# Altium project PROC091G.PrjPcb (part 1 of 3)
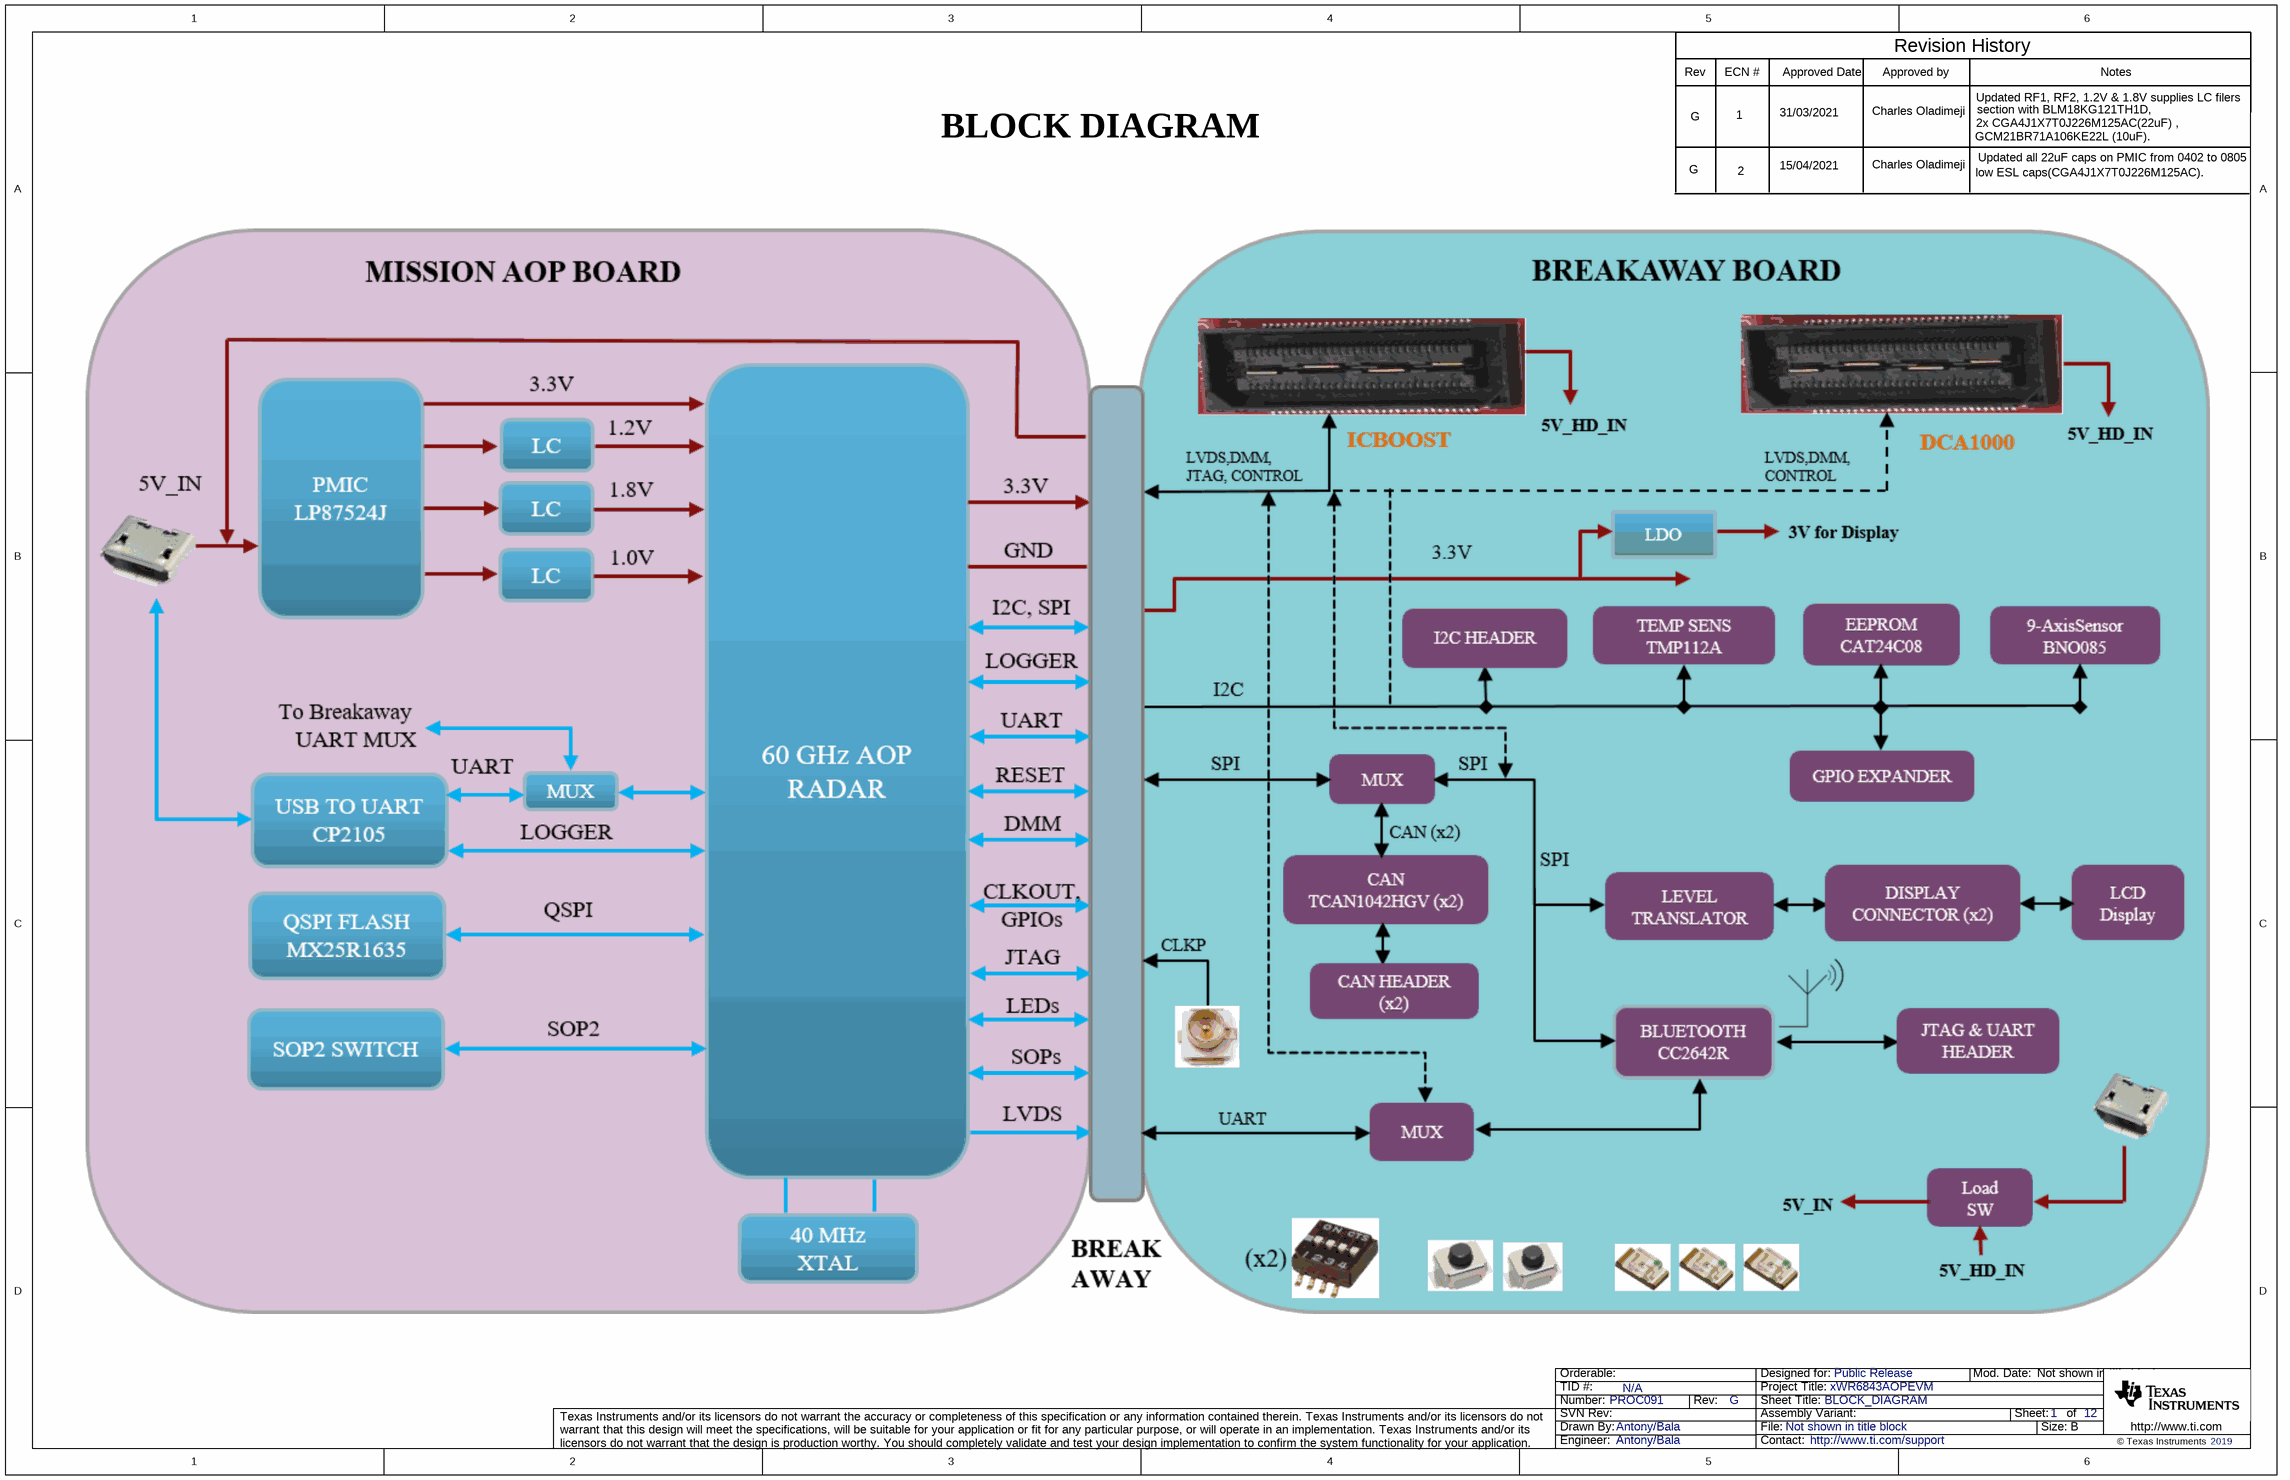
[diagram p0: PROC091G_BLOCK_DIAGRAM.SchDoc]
CopyrightYear: 2019; PCB_Layout: Mistral Team; PCB_Rev: G; PRJ_Customer: Public Release; PRJ_Engineer: Antony/Bala; PRJ_Number: PROC091; PRJ_Title: xWR6843AOPEVM; SCH_Rev: G; TechSupport: http://www.ti.com/support; TID: N/A
12 sheets, 442 parts. Net scope: flat (ports and power ports of the same name join across sheets).
Board file: PROC091G.PcbDoc
Sheets:
  PROC091G_BLOCK_DIAGRAM.SchDoc
  PROC091G_TABLEOFCONTENTS.SchDoc
  PROC091G_AOP_IO.SchDoc
  PROC091G_AOP_PWR.SchDoc
  PROC091G_PMIC.SchDoc
  PROC091G_FLASH_USB_TO_UART.SchDoc
  PROC091G_HD_CONN_PWR_SW.SchDoc
  PROC091G_RST_GPIOs_I2C.SchDoc
  PROC091G_BT_DISPLAY.SchDoc
  PROC091G_ANALOG_MUX.SchDoc
  PROC091G_CAN_INTERFACE.SchDoc
  PROC091G_Hardware.schdoc

## Sheet PROC091G_BLOCK_DIAGRAM.SchDoc: BLOCK_DIAGRAM
size 431 x 279 mm; Date: Not shown in title block; ApprovedBy: Not shown in title block; CheckedBy: Not shown in title block; Author: Not shown in title block; CompanyName: Not shown in title block; DrawnBy: Antony/Bala; Engineer: Not shown in title block; Organization: Not shown in title block; Address1: Not shown in title block; Address2: Not shown in title block; Address3: Not shown in title block; Address4: Not shown in title block; DocumentNumber: 1; Revision: Use project parameter SCH_Rev; SheetNumber: 1; SheetTotal: 12; PageSetup: Record=PageOptions¦CenterHorizontal=True¦CenterVertical=True¦PrintScale=1.00¦XCorrection=1.00¦YCorrection=1.00¦PrintKind=0¦BorderSize=5000000¦LeftOffset=0¦BottomOffset=0¦Orientation=2¦PaperLength=1000¦PaperWidth=1000¦Scale=100¦PaperSource=15¦PrintQuality=600¦MediaType=1¦DitherType=10¦PaperKind=Letter¦PrintScaleMode=1

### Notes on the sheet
- Rev
- ECN #
- Approved Date
- Approved by
- Revision History
- Updated RF1, RF2, 1.2V & 1.8V supplies LC filers
- Notes
- BLOCK DIAGRAM
- G
- 1
- 2
- 31/03/2021
- 15/04/2021
- Charles Oladimeji
- GCM21BR71A106KE22L (10uF).
- section with BLM18KG121TH1D,
- 2x CGA4J1X7T0J226M125AC(22uF) ,
- low ESL caps(CGA4J1X7T0J226M125AC).
- Updated all 22uF caps on PMIC from 0402 to 0805

## Sheet PROC091G_TABLEOFCONTENTS.SchDoc: TABLE_OF_CONTENTS
size 431 x 279 mm; Date: Not shown in title block; ApprovedBy: Not shown in title block; CheckedBy: Not shown in title block; Author: Not shown in title block; CompanyName: Not shown in title block; DrawnBy: Antony/Bala; Engineer: Not shown in title block; Organization: Not shown in title block; Address1: Not shown in title block; Address2: Not shown in title block; Address3: Not shown in title block; Address4: Not shown in title block; DocumentNumber: 2; Revision: Use project parameter SCH_Rev; SheetNumber: 2; SheetTotal: 12; PageSetup: Record=PageOptions¦CenterHorizontal=True¦CenterVertical=True¦PrintScale=1.00¦XCorrection=1.00¦YCorrection=1.00¦PrintKind=0¦BorderSize=5000000¦LeftOffset=0¦BottomOffset=0¦Orientation=2¦PaperLength=1000¦PaperWidth=1000¦Scale=100¦PaperSource=15¦PrintQuality=600¦MediaType=1¦DitherType=10¦PaperKind=Letter¦PrintScaleMode=1
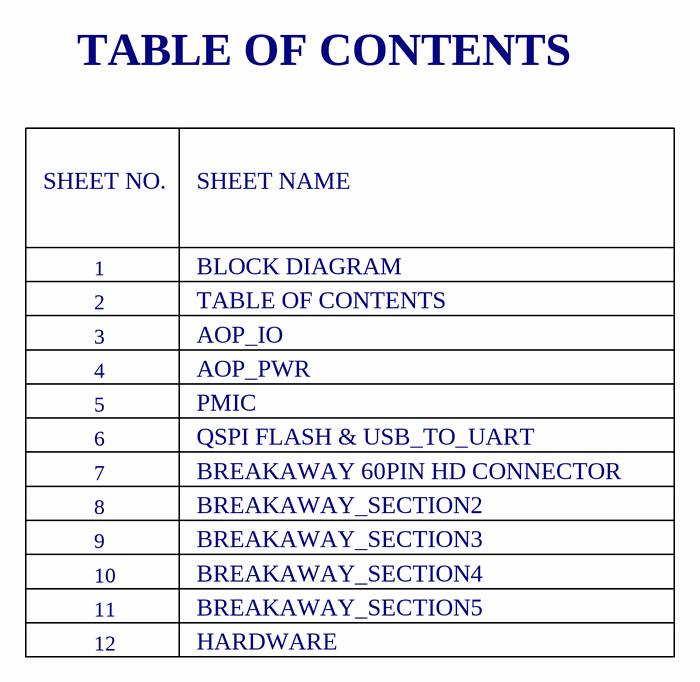
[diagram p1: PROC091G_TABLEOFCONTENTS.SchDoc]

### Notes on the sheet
- TABLE OF CONTENTS
- SHEET NO.
- SHEET NAME
- 1
- 2
- 3
- BLOCK DIAGRAM
- AOP_IO
- 4
- 5
- AOP_PWR
- PMIC
- 7
- 8
- 6
- QSPI FLASH & USB_TO_UART
- BREAKAWAY 60PIN HD CONNECTOR
- BREAKAWAY_SECTION2
- 9
- 10
- BREAKAWAY_SECTION3
- BREAKAWAY_SECTION4
- 11
- 12
- HARDWARE
- BREAKAWAY_SECTION5

## Sheet PROC091G_AOP_IO.SchDoc: AOP_IO
size 431 x 279 mm; Date: Not shown in title block; ApprovedBy: Not shown in title block; CheckedBy: Not shown in title block; Author: Not shown in title block; CompanyName: Not shown in title block; DrawnBy: Antony/Bala; Engineer: Not shown in title block; Organization: Not shown in title block; Address1: Not shown in title block; Address2: Not shown in title block; Address3: Not shown in title block; Address4: Not shown in title block; DocumentNumber: 3; Revision: Use project parameter SCH_Rev; SheetNumber: 3; SheetTotal: 12; PageSetup: Record=PageOptions¦CenterHorizontal=True¦CenterVertical=True¦PrintScale=1.00¦XCorrection=1.00¦YCorrection=1.00¦PrintKind=0¦BorderSize=5000000¦LeftOffset=0¦BottomOffset=0¦Orientation=2¦PaperLength=1000¦PaperWidth=1000¦Scale=100¦PaperSource=15¦PrintQuality=600¦MediaType=1¦DitherType=10¦PaperKind=Letter¦PrintScaleMode=1
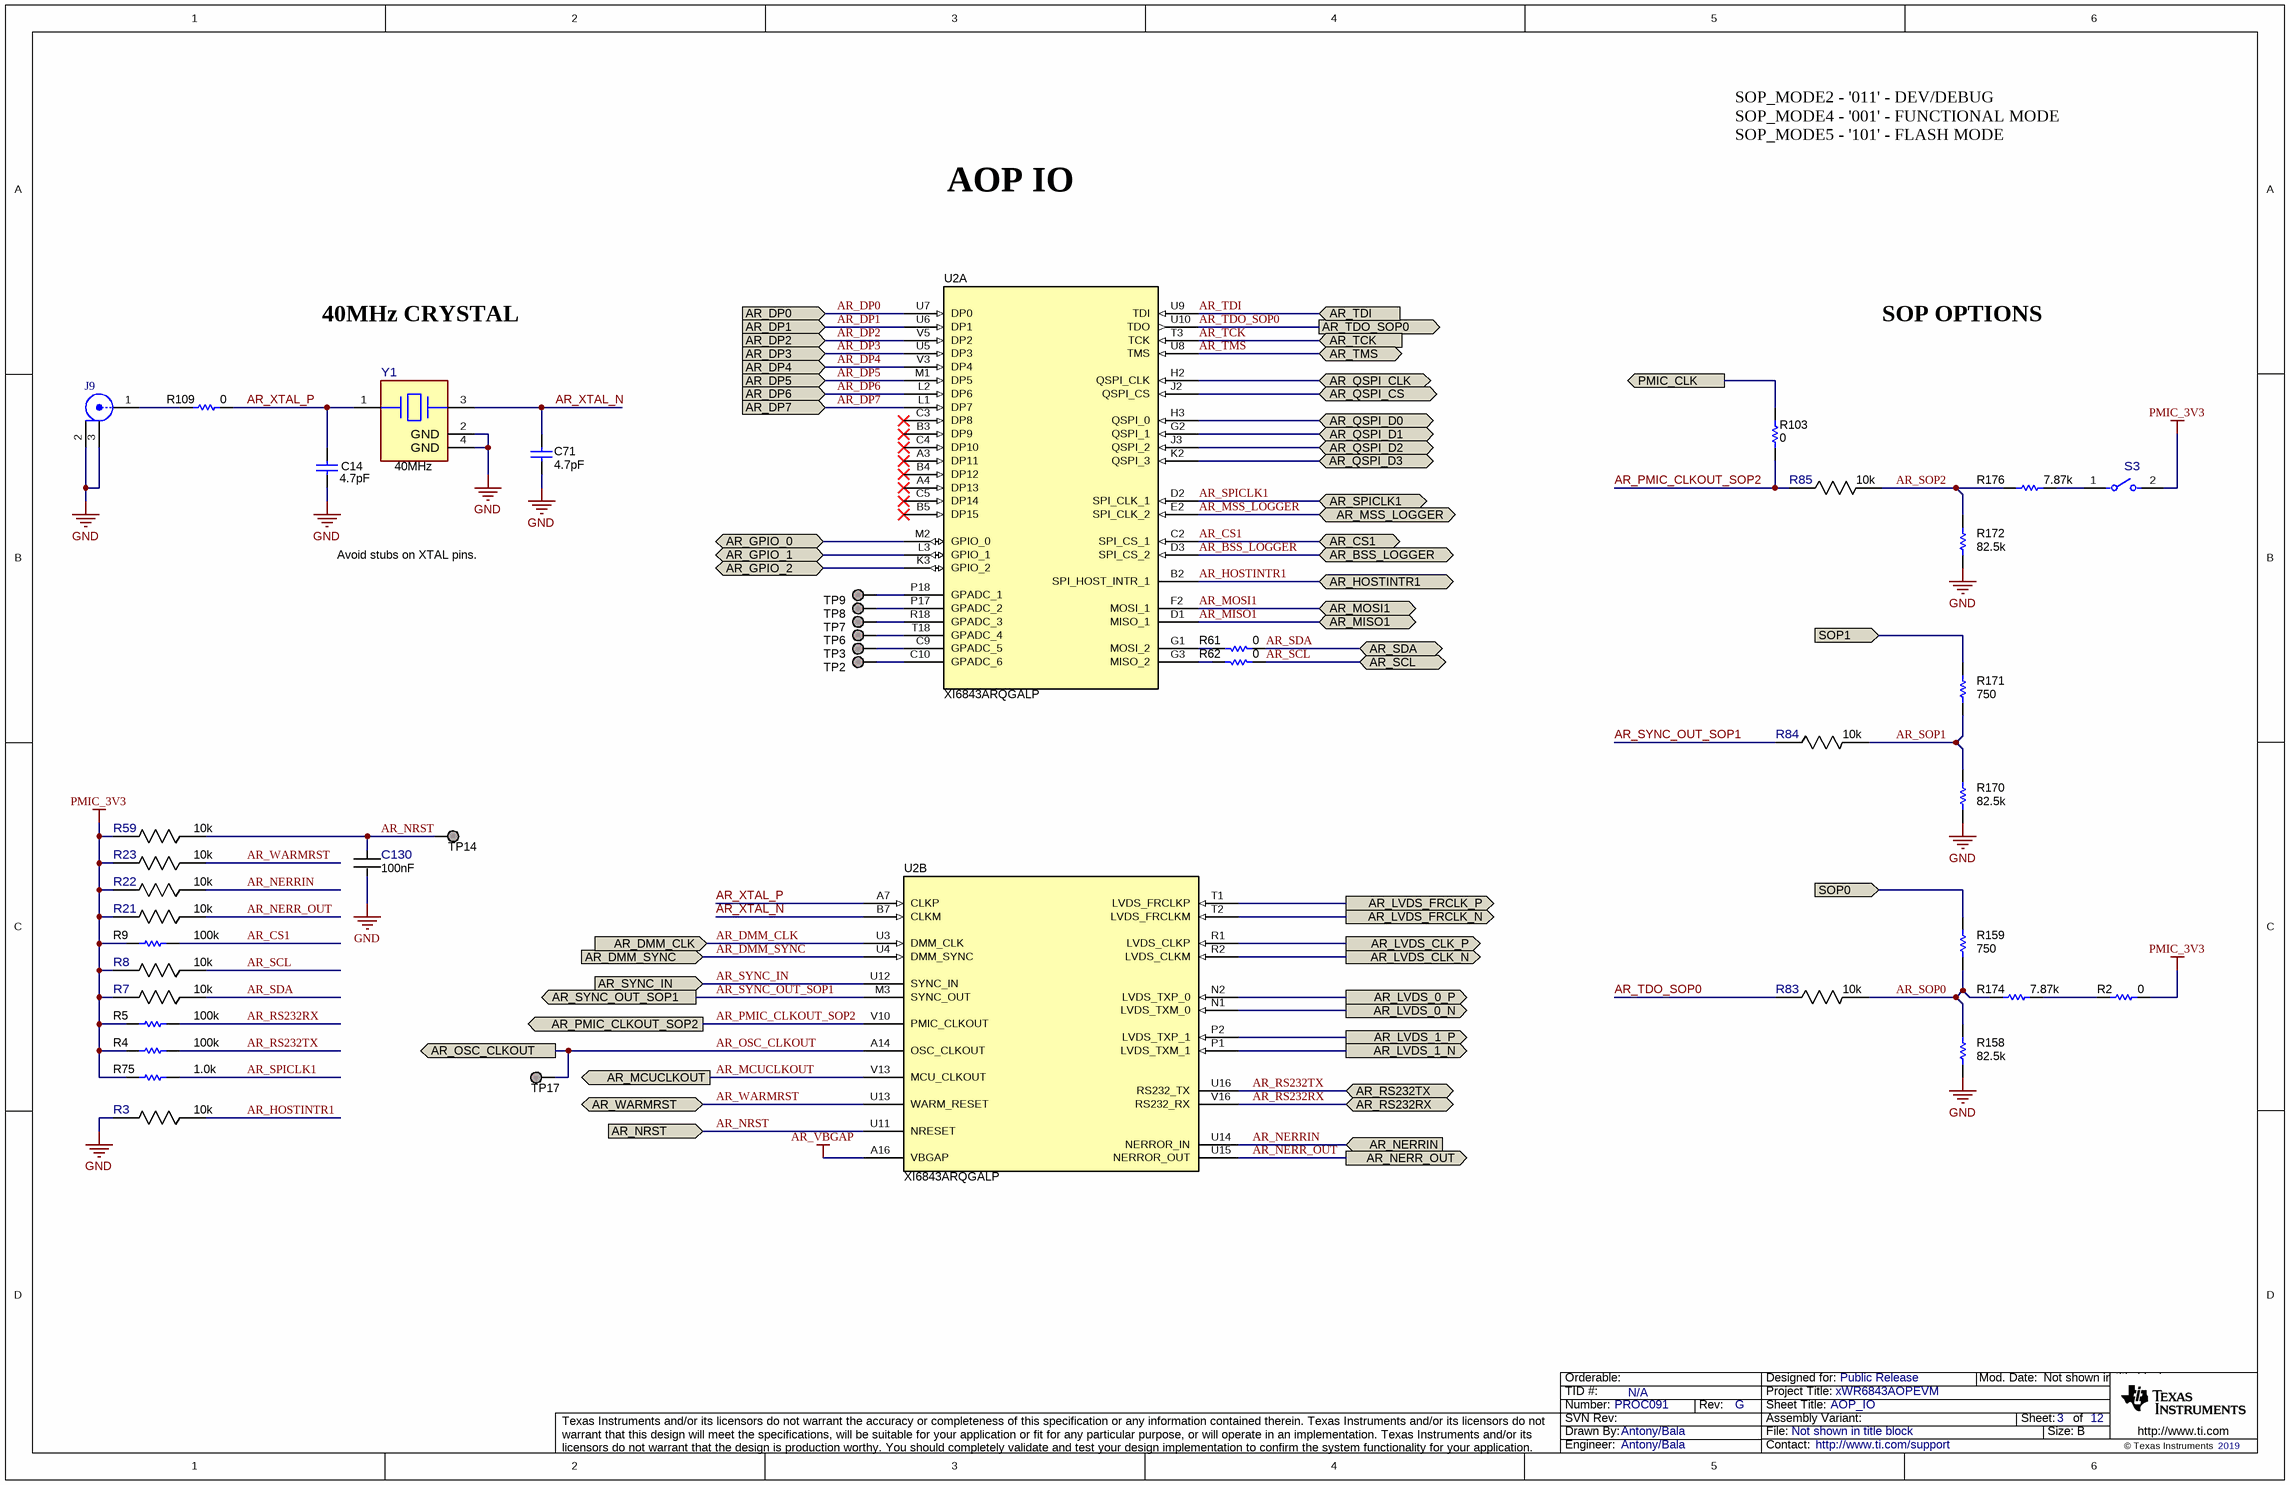
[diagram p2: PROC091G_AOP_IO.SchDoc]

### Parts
C14  value 4.7pF  [0201_033L]  (hidden comment: GRM0335C1H4R7BA01D)
C71  value 4.7pF  [0201_033L]  (hidden comment: GRM0335C1H4R7BA01D)
C130  Cap_F: 100nF  [FP-GRM033R6YA104KE14D_0201 (0603 Metric)-IPC_C]  (hidden comment: GRM033R6YA104KE14D)
J9  U.FL-R-SMT-1(01)  [CONN_UFL-R-SMT-1]  (value not drawn)
R2  Res_ohm: 0  [FP-RC0201JR-070RL_0201 (0603 Metric)-MFG]  (hidden comment: RC0201JR-070RL)
R3  Res_ohm: 10k  [FP-RR0306P-103-D_0201-IPC_C]  (hidden comment: RR0306P-103-D)
R4  value 100k  [0201L]  (hidden comment: CRCW0201100KFKED)
R5  value 100k  [0201L]  (hidden comment: CRCW0201100KFKED)
R7  Res_ohm: 10k  [FP-RR0306P-103-D_0201-IPC_C]  (hidden comment: RR0306P-103-D)
R8  Res_ohm: 10k  [FP-RR0306P-103-D_0201-IPC_C]  (hidden comment: RR0306P-103-D)
R9  value 100k  [0201L]  (hidden comment: CRCW0201100KFKED)
R21  Res_ohm: 10k  [FP-RR0306P-103-D_0201-IPC_C]  (hidden comment: RR0306P-103-D)
R22  Res_ohm: 10k  [FP-RR0306P-103-D_0201-IPC_C]  (hidden comment: RR0306P-103-D)
R23  Res_ohm: 10k  [FP-RR0306P-103-D_0201-IPC_C]  (hidden comment: RR0306P-103-D)
R59  Res_ohm: 10k  [FP-RR0306P-103-D_0201-IPC_C]  (hidden comment: RR0306P-103-D)
R61  Res_ohm: 0  [FP-RC0201JR-070RL_0201 (0603 Metric)-MFG]  (hidden comment: RC0201JR-070RL)
R62  Res_ohm: 0  [FP-RC0201JR-070RL_0201 (0603 Metric)-MFG]  (hidden comment: RC0201JR-070RL)
R75  value 1.0k  [0201L]  (hidden comment: RC0201JR-071KL)
R83  Res_ohm: 10k  [FP-RR0306P-103-D_0201-IPC_C]  (hidden comment: RR0306P-103-D)
R84  Res_ohm: 10k  [FP-RR0306P-103-D_0201-IPC_C]  (hidden comment: RR0306P-103-D)
R85  Res_ohm: 10k  [FP-RR0306P-103-D_0201-IPC_C]  (hidden comment: RR0306P-103-D)
R103  Res_ohm: 0  [FP-RC0201JR-070RL_0201 (0603 Metric)-IPC_C]  (hidden comment: RC0201JR-070RL)
R109  Res_ohm: 0  [FP-RC0201JR-070RL_0201 (0603 Metric)-MFG]  (hidden comment: RC0201JR-070RL)
R158  value 82.5k  [0201L]  (hidden comment: RC0201FR-0782K5L)
R159  value 750  [0201L]  (hidden comment: RC0201JR-07750RL)
R170  value 82.5k  [0201L]  (hidden comment: RC0201FR-0782K5L)
R171  value 750  [0201L]  (hidden comment: RC0201JR-07750RL)
R172  value 82.5k  [0201L]  (hidden comment: RC0201FR-0782K5L)
R174  value 7.87k  [0201L]  (hidden comment: RC0201FR-077K87L)
R176  value 7.87k  [0201L]  (hidden comment: RC0201FR-077K87L)
S3  CHS-01TA  [FP-CHS-01TA_SMT_SW_5MM4_2MM5-MFG]  (value not drawn)
TP2  TESTPOINT  [TP_25MIL-SMT]  (value not drawn)  (no BOM)
TP3  TESTPOINT  [TP_25MIL-SMT]  (value not drawn)  (no BOM)
TP6  TESTPOINT  [TP_25MIL-SMT]  (value not drawn)  (no BOM)
TP7  TESTPOINT  [TP_25MIL-SMT]  (value not drawn)  (no BOM)
TP8  TESTPOINT  [TP_25MIL-SMT]  (value not drawn)  (no BOM)
TP9  TESTPOINT  [TP_25MIL-SMT]  (value not drawn)  (no BOM)
TP14  TESTPOINT  [TP_25MIL-SMT]  (value not drawn)  (no BOM)
TP17  TESTPOINT  [TP_25MIL-SMT]  (value not drawn)  (no BOM)
U2  XI6843ARQGALP  [ALP0180A]  (parts A,B of 4)
Y1  Frequency_Fixed: 40MHz  [FP-CX2016DB40000D0FLJCC_SMT_2MM0_1MM6-MFG]  (hidden comment: CX2016DB40000D0FLJCC)

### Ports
AR_BSS_LOGGER (bidir), AR_CS1 (bidir), AR_DMM_CLK (in), AR_DMM_SYNC (in), AR_DP0 (in), AR_DP1 (in), AR_DP2 (in), AR_DP3 (in), AR_DP4 (in), AR_DP5 (in), AR_DP6 (in), AR_DP7 (in), AR_GPIO_0 (bidir), AR_GPIO_1 (bidir), AR_GPIO_2 (bidir), AR_HOSTINTR1 (bidir), AR_LVDS_0_N (out), AR_LVDS_0_P (out), AR_LVDS_1_N (out), AR_LVDS_1_P (out), AR_LVDS_CLK_N (out), AR_LVDS_CLK_P (out), AR_LVDS_FRCLK_N (out), AR_LVDS_FRCLK_P (out), AR_MCUCLKOUT (out), AR_MISO1 (bidir), AR_MOSI1 (bidir), AR_MSS_LOGGER (bidir), AR_NERR_OUT (out), AR_NERRIN (in), AR_NRST (in), AR_OSC_CLKOUT (out), AR_PMIC_CLKOUT_SOP2 (out), AR_QSPI_CLK (bidir), AR_QSPI_CS (bidir), AR_QSPI_D0 (bidir), AR_QSPI_D1 (bidir), AR_QSPI_D2 (bidir), AR_QSPI_D3 (bidir), AR_RS232RX (bidir), AR_RS232TX (bidir), AR_SCL (bidir), AR_SDA (bidir), AR_SPICLK1 (bidir), AR_SYNC_IN (in), AR_SYNC_OUT_SOP1 (out), AR_TCK (in), AR_TDI (in), AR_TDO_SOP0 (out), AR_TMS (bidir), AR_WARMRST (bidir), PMIC_CLK (out), SOP0 (in), SOP1 (in)

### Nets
AR_VBGAP: U2.A16(VBGAP)
GND: C14.1 C71.1 C130.2 J9.2 J9.3 R3.2 R158.1 R170.1 R172.1 Y1.2(GND) Y1.4(GND)
PMIC_3V3: R2.1 R4.1 R5.1 R7.2 R8.2 R9.1 R21.2 R22.2 R23.2 R59.2 R75.1 S3.2
AR_BSS_LOGGER: U2.D3(SPI_CS_2) ; port AR_BSS_LOGGER
AR_CS1: R9.2 U2.C2(SPI_CS_1) ; port AR_CS1
AR_DMM_CLK: U2.U3(DMM_CLK) ; port AR_DMM_CLK
AR_DMM_SYNC: U2.U4(DMM_SYNC) ; port AR_DMM_SYNC
AR_DP0: U2.U7(DP0) ; port AR_DP0
AR_DP1: U2.U6(DP1) ; port AR_DP1
AR_DP2: U2.V5(DP2) ; port AR_DP2
AR_DP3: U2.U5(DP3) ; port AR_DP3
AR_DP4: U2.V3(DP4) ; port AR_DP4
AR_DP5: U2.M1(DP5) ; port AR_DP5
AR_DP6: U2.L2(DP6) ; port AR_DP6
AR_DP7: U2.L1(DP7) ; port AR_DP7
AR_GPIO_0: U2.M2(GPIO_0) ; port AR_GPIO_0
AR_GPIO_1: U2.L3(GPIO_1) ; port AR_GPIO_1
AR_GPIO_2: U2.K3(GPIO_2) ; port AR_GPIO_2
AR_HOSTINTR1: R3.1 U2.B2(SPI_HOST_INTR_1) ; port AR_HOSTINTR1
AR_LVDS_0_N: U2.N1(LVDS_TXM_0) ; port AR_LVDS_0_N
AR_LVDS_0_P: U2.N2(LVDS_TXP_0) ; port AR_LVDS_0_P
AR_LVDS_1_N: U2.P1(LVDS_TXM_1) ; port AR_LVDS_1_N
AR_LVDS_1_P: U2.P2(LVDS_TXP_1) ; port AR_LVDS_1_P
AR_LVDS_CLK_N: U2.R2(LVDS_CLKM) ; port AR_LVDS_CLK_N
AR_LVDS_CLK_P: U2.R1(LVDS_CLKP) ; port AR_LVDS_CLK_P
AR_LVDS_FRCLK_N: U2.T2(LVDS_FRCLKM) ; port AR_LVDS_FRCLK_N
AR_LVDS_FRCLK_P: U2.T1(LVDS_FRCLKP) ; port AR_LVDS_FRCLK_P
AR_MCUCLKOUT: U2.V13(MCU_CLKOUT) ; port AR_MCUCLKOUT
AR_MISO1: U2.D1(MISO_1) ; port AR_MISO1
AR_MOSI1: U2.F2(MOSI_1) ; port AR_MOSI1
AR_MSS_LOGGER: U2.E2(SPI_CLK_2) ; port AR_MSS_LOGGER
AR_NERR_OUT: R21.1 U2.U15(NERROR_OUT) ; port AR_NERR_OUT
AR_NERRIN: R22.1 U2.U14(NERROR_IN) ; port AR_NERRIN
AR_NRST: C130.1 R59.1 TP14.1 U2.U11(NRESET) ; port AR_NRST
AR_OSC_CLKOUT: TP17.1 U2.A14(OSC_CLKOUT) ; port AR_OSC_CLKOUT
AR_PMIC_CLKOUT_SOP2: R85.1 R103.1 U2.V10(PMIC_CLKOUT) ; port AR_PMIC_CLKOUT_SOP2
AR_QSPI_CLK: U2.H2(QSPI_CLK) ; port AR_QSPI_CLK
AR_QSPI_CS: U2.J2(QSPI_CS) ; port AR_QSPI_CS
AR_QSPI_D0: U2.H3(QSPI_0) ; port AR_QSPI_D0
AR_QSPI_D1: U2.G2(QSPI_1) ; port AR_QSPI_D1
AR_QSPI_D2: U2.J3(QSPI_2) ; port AR_QSPI_D2
AR_QSPI_D3: U2.K2(QSPI_3) ; port AR_QSPI_D3
AR_RS232RX: R5.2 U2.V16(RS232_RX) ; port AR_RS232RX
AR_RS232TX: R4.2 U2.U16(RS232_TX) ; port AR_RS232TX
AR_SCL: R8.1 R62.2 ; port AR_SCL
AR_SDA: R7.1 R61.2 ; port AR_SDA
AR_SOP0: R83.2 R158.2 R159.1 R174.2
AR_SOP1: R84.2 R170.2 R171.1
AR_SOP2: R85.2 R172.2 R176.2
AR_SPICLK1: R75.2 U2.D2(SPI_CLK_1) ; port AR_SPICLK1
AR_SYNC_IN: U2.U12(SYNC_IN) ; port AR_SYNC_IN
AR_SYNC_OUT_SOP1: R84.1 U2.M3(SYNC_OUT) ; port AR_SYNC_OUT_SOP1
AR_TCK: U2.T3(TCK) ; port AR_TCK
AR_TDI: U2.U9(TDI) ; port AR_TDI
AR_TDO_SOP0: R83.1 U2.U10(TDO) ; port AR_TDO_SOP0
AR_TMS: U2.U8(TMS) ; port AR_TMS
AR_WARMRST: R23.1 U2.U13(WARM_RESET) ; port AR_WARMRST
AR_XTAL_N: C71.2 U2.B7(CLKM) Y1.3
AR_XTAL_P: C14.2 R109.1 U2.A7(CLKP) Y1.1
PMIC_CLK: R103.2 ; port PMIC_CLK
SOP0: R159.2 ; port SOP0
SOP1: R171.2 ; port SOP1
NetJ9_1: J9.1 R109.2
NetR2_2: R2.2 R174.1
NetR61_1: R61.1 U2.G1(MOSI_2)
NetR62_1: R62.1 U2.G3(MISO_2)
NetR176_1: R176.1 S3.1
NetTP2_1: TP2.1 U2.C10(GPADC_6)
NetTP3_1: TP3.1 U2.C9(GPADC_5)
NetTP6_1: TP6.1 U2.T18(GPADC_4)
NetTP7_1: TP7.1 U2.R18(GPADC_3)
NetTP8_1: TP8.1 U2.P17(GPADC_2)
NetTP9_1: TP9.1 U2.P18(GPADC_1)

Not connected (* = marked no-connect by the designer): U2 A3(DP11)* A4(DP13)* B3(DP9)* B4(DP12)* B5(DP15)* C3(DP8)* C4(DP10)* C5(DP14)*

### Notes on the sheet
- SOP_MODE2 - '011' - DEV/DEBUG
  SOP_MODE4 - '001' - FUNCTIONAL MODE
  SOP_MODE5 - '101' - FLASH MODE
- AOP IO
- 40MHz CRYSTAL
- SOP OPTIONS
- Avoid stubs on XTAL pins.

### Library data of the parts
C14 C71 = CMP-0080076-1: CAP, CERM, 4.7 pF, 50 V,+/- 3%, C0G/NP0, 0201; Manufacturer: MuRata; AEC Category: Q200; AEC Qualified: N; Cap_Case: 0201; SizeArea_mm2: 0.18; SizeAreaWB_mm2: 2.08; SizeX_mm: 0.6; SizeY_mm: 0.3; SizeZ_mm: 0.33; TaMax_C: 125°C; TaMin_C: -55°C; U/M: EA; Value2: 50V
C130 = CMP-0086440-1: Cap Ceramic 0.1uF 35V X5R 10% Pad SMD 0201 85C T/R; Manufacturer: Murata Electronics North America; AEC Qualified: No; SizeZ_mm: 0.33mm; Symbol Name: SYM-GRM033R6YA104KE14D; TempCo: 15%
J9 = CMP-0075320-1: Receptacle, Ultra Miniature Coaxial, Male Pin, 50 ohm, SMT; Manufacturer: Hirose Electric Co. Ltd.; CNHeader: False; Gender: Female; ContactFinish: Gold
R2 R61 R62 R103 R109 = CMP-0086442-2: RES SMD 0 OHM JUMPER 1/20W 0201; Manufacturer: Yageo; AEC Qualified: No; Power_W: 50mW; SizeZ_mm: 0.26mm; TempCo: 200ppm/°C; Tolerance_%: 5%; VDC_V: 25V
R3 R7 R8 R21-R23 R59 R83-R85 = CMP-0088002-1: 10 kOhms ±0.5% 0.05W, 1/20W Chip Resistor 0201 (0603 Metric)  Thin Film; Manufacturer: Susumu; AEC Qualified: No; Power_W: 50mW; SizeZ_mm: 0.26mm; Symbol Name: SYM-RR0306P-103-D; TempCo: 25ppm/°C; VDC_V: 15V
R4 R5 R9 = CMP-0027261-3: RES, 100 k, 1%, 0.05 W, 0201; Manufacturer: Vishay-Dale; AEC Category: Q200; AEC Qualified: N; EIA_Code: E96; Power_W: 50mW; SizeArea_mm2: 0.18; SizeX_mm: 0.6; SizeY_mm: 0.3; SizeZ_mm: 0.26; TempCo: 100 ppm/C; Value2: 0.05W; VDC_V: 30V
R75 = CMP-0027052-1: RES, 1.0 k, 5%, 0.05 W, 0201; Manufacturer: Yageo America; AEC Category: Q200; AEC Qualified: N; EIA_Code: E24; Power_W: 50mW; Res_ohm: 1k; SizeArea_mm2: 0.18; SizeX_mm: 0.6; SizeY_mm: 0.3; SizeZ_mm: 0.26; TempCo: 200 ppm/C; U/M: EA; Value2: 0.05W; Value_Code: 1k00; VDC_V: 25V
R158 R170 R172 = CMP-0027891-1: RES, 82.5 k, 1%, 0.05 W, 0201; Manufacturer: Yageo America; AEC Category: Q200; AEC Qualified: N; EIA_Code: E96; Power_W: 50mW; SizeArea_mm2: 0.18; SizeX_mm: 0.6; SizeY_mm: 0.3; SizeZ_mm: 0.26; TempCo: 200 ppm/C; U/M: EA; Value2: 0.05W; Value_Code: 82k5; VDC_V: 25V
R159 R171 = CMP-0027165-1: RES, 750, 5%, 0.05 W, 0201; Manufacturer: Yageo America; AEC Category: Q200; AEC Qualified: N; EIA_Code: E24; Power_W: 50mW; SizeArea_mm2: 0.18; SizeX_mm: 0.6; SizeY_mm: 0.3; SizeZ_mm: 0.26; TempCo: 200 ppm/C; U/M: EA; Value2: 0.05W; Value_Code: 750R; VDC_V: 25V
R174 R176 = CMP-0027880-1: RES, 7.87 k, 1%, 0.05 W, 0201; Manufacturer: Yageo America; AEC Category: Q200; AEC Qualified: N; EIA_Code: E96; Power_W: 50mW; SizeArea_mm2: 0.18; SizeX_mm: 0.6; SizeY_mm: 0.3; SizeZ_mm: 0.26; TempCo: 200 ppm/C; U/M: EA; Value2: 0.05W; Value_Code: 7k87; VDC_V: 25V
S3 = CMP-0087181-1: SWITCH SLIDE DIP SPST 100MA 6V; Manufacturer: Nidec Copal Electronics; PositionCount: 1; SizeZ_mm: 2.5mm; Symbol Name: SYM-CHS-01TA
TP2 TP3 TP6-TP9 TP14 TP17 = CMP-0078143-3: TEST POINT.  No entry in BOM.
U2 = CMP-0860942-2: XI6843ARQGALP, ALP0180A (BGA-180); Manufacturer: Texas Instruments; SizeZ_mm: 0.965; SizeX_mm: 15; AEC Qualified: N; SizeArea_mm2: 225; SizeAreaWB_mm2: 289; CompType: IC; AEC Category: Q200
Y1 = CMP-0087164-1: CRYSTAL 40.0000MHZ 8PF SMD; Manufacturer: Kyocera International Inc. Electronic Components; AEC Qualified: No; Frequency Stability: 15ppm; SizeZ_mm: 0.45mm

## Sheet PROC091G_AOP_PWR.SchDoc: AOP_POWER
size 431 x 279 mm; Date: Not shown in title block; ApprovedBy: Not shown in title block; CheckedBy: Not shown in title block; Author: Not shown in title block; CompanyName: Not shown in title block; DrawnBy: Antony/Bala; Engineer: Not shown in title block; Organization: Not shown in title block; Address1: Not shown in title block; Address2: Not shown in title block; Address3: Not shown in title block; Address4: Not shown in title block; DocumentNumber: 4; Revision: Use project parameter SCH_Rev; SheetNumber: 4; SheetTotal: 12; PageSetup: Record=PageOptions¦CenterHorizontal=True¦CenterVertical=True¦PrintScale=1.00¦XCorrection=1.00¦YCorrection=1.00¦PrintKind=0¦BorderSize=5000000¦LeftOffset=0¦BottomOffset=0¦Orientation=2¦PaperLength=1000¦PaperWidth=1000¦Scale=100¦PaperSource=15¦PrintQuality=600¦MediaType=1¦DitherType=10¦PaperKind=Letter¦PrintScaleMode=1
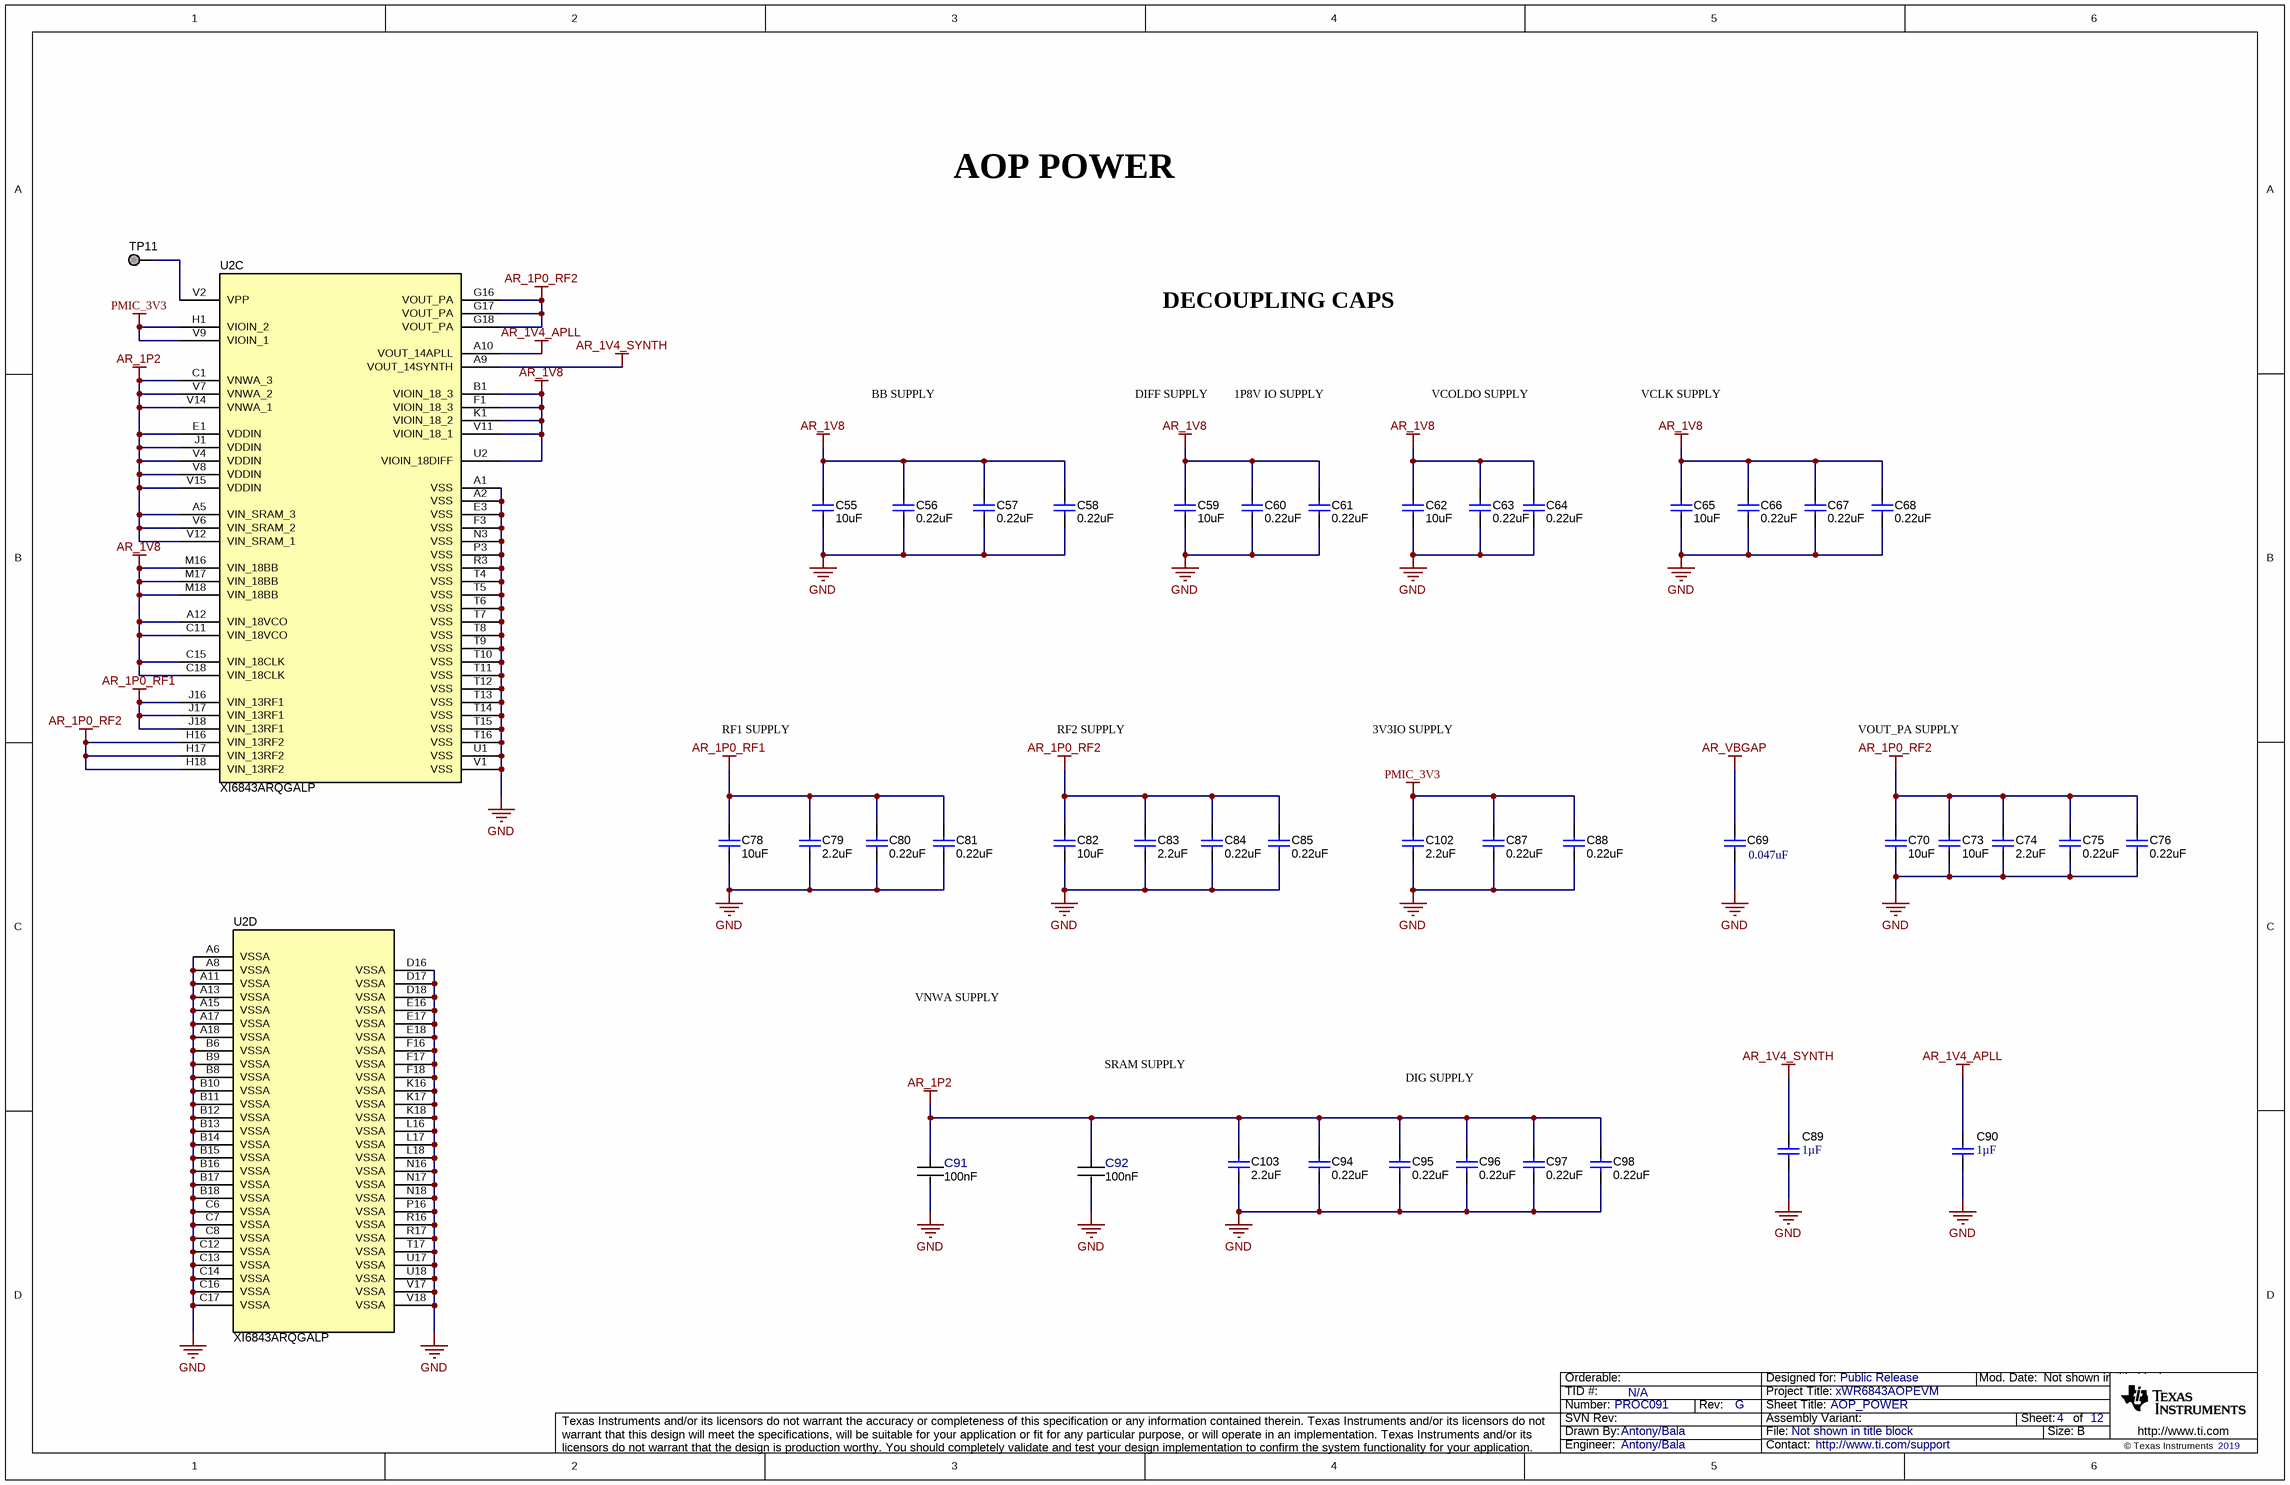
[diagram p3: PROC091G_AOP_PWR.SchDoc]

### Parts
C55  value 10uF  [0402_070]  (hidden comment: CL05A106MP5NUNC)
C56  value 0.22uF  [0201_033L]  (hidden comment: LMK063BJ224MP-F)
C57  value 0.22uF  [0201_033L]  (hidden comment: LMK063BJ224MP-F)
C58  value 0.22uF  [0201_033L]  (hidden comment: LMK063BJ224MP-F)
C59  value 10uF  [0402_070]  (hidden comment: CL05A106MP5NUNC)
C60  value 0.22uF  [0201_033L]  (hidden comment: LMK063BJ224MP-F)
C61  value 0.22uF  [0201_033L]  (hidden comment: LMK063BJ224MP-F)
C62  value 10uF  [0402_070]  (hidden comment: CL05A106MP5NUNC)
C63  value 0.22uF  [0201_033L]  (hidden comment: LMK063BJ224MP-F)
C64  value 0.22uF  [0201_033L]  (hidden comment: LMK063BJ224MP-F)
C65  value 10uF  [0402_070]  (hidden comment: CL05A106MP5NUNC)
C66  value 0.22uF  [0201_033L]  (hidden comment: LMK063BJ224MP-F)
C67  value 0.22uF  [0201_033L]  (hidden comment: LMK063BJ224MP-F)
C68  value 0.22uF  [0201_033L]  (hidden comment: LMK063BJ224MP-F)
C69  ValueDisplayed: 0.047uF  [0201_033L]  (hidden comment: GRM033R61C473KE84D)
C70  value 10uF  [0402_070]  (hidden comment: CL05A106MP5NUNC)
C73  value 10uF  [0402_070]  (hidden comment: CL05A106MP5NUNC)
C74  value 2.2uF  [0201L]  (hidden comment: CL03A225MQ3CRNC)
C75  value 0.22uF  [0201_033L]  (hidden comment: LMK063BJ224MP-F)
C76  value 0.22uF  [0201_033L]  (hidden comment: LMK063BJ224MP-F)
C78  value 10uF  [0402_070]  (hidden comment: CL05A106MP5NUNC)
C79  value 2.2uF  [0201L]  (hidden comment: CL03A225MQ3CRNC)
C80  value 0.22uF  [0201_033L]  (hidden comment: LMK063BJ224MP-F)
C81  value 0.22uF  [0201_033L]  (hidden comment: LMK063BJ224MP-F)
C82  value 10uF  [0402_070]  (hidden comment: CL05A106MP5NUNC)
C83  value 2.2uF  [0201L]  (hidden comment: CL03A225MQ3CRNC)
C84  value 0.22uF  [0201_033L]  (hidden comment: LMK063BJ224MP-F)
C85  value 0.22uF  [0201_033L]  (hidden comment: LMK063BJ224MP-F)
C87  value 0.22uF  [0201_033L]  (hidden comment: LMK063BJ224MP-F)
C88  value 0.22uF  [0201_033L]  (hidden comment: LMK063BJ224MP-F)
C89  ValueDisplayed: 1µF  [0402L]  (hidden comment: CGB2A1X6S0J105K033BC)
C90  ValueDisplayed: 1µF  [0402L]  (hidden comment: CGB2A1X6S0J105K033BC)
C91  Cap_F: 100nF  [FP-GRM033R6YA104KE14D_0201 (0603 Metric)-IPC_C]  (hidden comment: GRM033R6YA104KE14D)
C92  Cap_F: 100nF  [FP-GRM033R6YA104KE14D_0201 (0603 Metric)-IPC_C]  (hidden comment: GRM033R6YA104KE14D)
C94  value 0.22uF  [0201_033L]  (hidden comment: LMK063BJ224MP-F)
C95  value 0.22uF  [0201_033L]  (hidden comment: LMK063BJ224MP-F)
C96  value 0.22uF  [0201_033L]  (hidden comment: LMK063BJ224MP-F)
C97  value 0.22uF  [0201_033L]  (hidden comment: LMK063BJ224MP-F)
C98  value 0.22uF  [0201_033L]  (hidden comment: LMK063BJ224MP-F)
C102  value 2.2uF  [0201L]  (hidden comment: CL03A225MQ3CRNC)
C103  value 2.2uF  [0201L]  (hidden comment: CL03A225MQ3CRNC)
TP11  TP_SM_1MM  [TP_SM_1MM]  (value not drawn)  (no BOM)
U2  XI6843ARQGALP  [ALP0180A]  (parts C,D of 4)

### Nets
AR_1P0_RF1: C78.1 C79.1 C80.1 C81.1 U2.J16(VIN_13RF1) U2.J17(VIN_13RF1) U2.J18(VIN_13RF1)
AR_1P0_RF2: C70.1 C73.1 C74.1 C75.1 C76.1 C82.1 C83.1 C84.1 C85.1 U2.G16(VOUT_PA) U2.G17(VOUT_PA) U2.G18(VOUT_PA) U2.H16(VIN_13RF2) U2.H17(VIN_13RF2) U2.H18(VIN_13RF2)
AR_1P2: C91.1 C92.1 C94.1 C95.1 C96.1 C97.1 C98.1 C103.1 U2.A5(VIN_SRAM_3) U2.C1(VNWA_3) U2.E1(VDDIN) U2.J1(VDDIN) U2.V4(VDDIN) U2.V6(VIN_SRAM_2) U2.V7(VNWA_2) U2.V8(VDDIN) U2.V12(VIN_SRAM_1) U2.V14(VNWA_1) U2.V15(VDDIN)
AR_1V4_APLL: C90.1 U2.A10(VOUT_14APLL)
AR_1V4_SYNTH: C89.1 U2.A9(VOUT_14SYNTH)
AR_1V8: C55.1 C56.1 C57.1 C58.1 C59.1 C60.1 C61.1 C62.1 C63.1 C64.1 C65.1 C66.1 C67.1 C68.1 U2.A12(VIN_18VCO) U2.B1(VIOIN_18_3) U2.C11(VIN_18VCO) U2.C15(VIN_18CLK) U2.C18(VIN_18CLK) U2.F1(VIOIN_18_3) U2.K1(VIOIN_18_2) U2.M16(VIN_18BB) U2.M17(VIN_18BB) U2.M18(VIN_18BB) U2.U2(VIOIN_18DIFF) U2.V11(VIOIN_18_1)
AR_VBGAP: C69.1
GND: C55.2 C56.2 C57.2 C58.2 C59.2 C60.2 C61.2 C62.2 C63.2 C64.2 C65.2 C66.2 C67.2 C68.2 C69.2 C70.2 C73.2 C74.2 C75.2 C76.2 C78.2 C79.2 C80.2 C81.2 C82.2 C83.2 C84.2 C85.2 C87.2 C88.2 C89.2 C90.2 C91.2 C92.2 C94.2 C95.2 C96.2 C97.2 C98.2 C102.2 C103.2 U2.A1(VSS) U2.A2(VSS) U2.A6(VSSA) U2.A8(VSSA) U2.A11(VSSA) U2.A13(VSSA) U2.A15(VSSA) U2.A17(VSSA) U2.A18(VSSA) U2.B6(VSSA) U2.B8(VSSA) U2.B9(VSSA) U2.B10(VSSA) U2.B11(VSSA) U2.B12(VSSA) U2.B13(VSSA) U2.B14(VSSA) U2.B15(VSSA) U2.B16(VSSA) U2.B17(VSSA) U2.B18(VSSA) U2.C6(VSSA) U2.C7(VSSA) U2.C8(VSSA) U2.C12(VSSA) U2.C13(VSSA) U2.C14(VSSA) U2.C16(VSSA) U2.C17(VSSA) U2.D16(VSSA) U2.D17(VSSA) U2.D18(VSSA) U2.E3(VSS) U2.E16(VSSA) U2.E17(VSSA) U2.E18(VSSA) U2.F3(VSS) U2.F16(VSSA) U2.F17(VSSA) U2.F18(VSSA) U2.K16(VSSA) U2.K17(VSSA) U2.K18(VSSA) U2.L16(VSSA) U2.L17(VSSA) U2.L18(VSSA) U2.N3(VSS) U2.N16(VSSA) U2.N17(VSSA) U2.N18(VSSA) U2.P3(VSS) U2.P16(VSSA) U2.R3(VSS) U2.R16(VSSA) U2.R17(VSSA) U2.T4(VSS) U2.T5(VSS) U2.T6(VSS) U2.T7(VSS) U2.T8(VSS) U2.T9(VSS) U2.T10(VSS) U2.T11(VSS) U2.T12(VSS) U2.T13(VSS) U2.T14(VSS) U2.T15(VSS) U2.T16(VSS) U2.T17(VSSA) U2.U1(VSS) U2.U17(VSSA) U2.U18(VSSA) U2.V1(VSS) U2.V17(VSSA) U2.V18(VSSA)
PMIC_3V3: C87.1 C88.1 C102.1 U2.H1(VIOIN_2) U2.V9(VIOIN_1)
NetTP11_1: TP11.1 U2.V2(VPP)

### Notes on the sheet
- AOP POWER
- DECOUPLING CAPS
- BB SUPPLY
- DIFF SUPPLY
- 1P8V IO SUPPLY
- VCOLDO SUPPLY
- VCLK SUPPLY
- RF1 SUPPLY
- RF2 SUPPLY
- 3V3IO SUPPLY
- VOUT_PA SUPPLY
- VNWA SUPPLY
- SRAM SUPPLY
- DIG SUPPLY

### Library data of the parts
C55 C59 C62 C65 C70 C73 C78 C82 = CMP-0006339-4: CAP, CERM, 10 uF, 10 V, +/- 20%, X5R, 0402; Manufacturer: Samsung Electro-Mechanics; AEC Category: Q200; AEC Qualified: N; Cap_Case: 0402; Cap_F: 10µF; SizeArea_mm2: 0.5; SizeAreaWB_mm2: 3; SizeX_mm: 1; SizeZ_mm: 0.6; TaMax_C: 85°C; TaMin_C: -55°C; U/M: EA; Value1: Unknown; Value2: 10V
C56-C58 C60 C61 C63 C64 C66-C68 C75 C76 C80 C81 C84 C85 C87 C88 C94-C98 = CMP-0009781-1: CAP, CERM, 0.22 uF, 10 V, +/- 20%, X5R, 0201; Manufacturer: Taiyo Yuden; AEC Category: Q200; AEC Qualified: N; Cap_Case: 0201; Cap_F: 220nF; SizeArea_mm2: 0.18; SizeAreaWB_mm2: 2.08; SizeX_mm: 0.6; SizeY_mm: 0.3; SizeZ_mm: 0.33; TaMax_C: 85°C; TaMin_C: -55°C; U/M: EA; Value1: Unknown; Value2: 10V
C69 = CMP-0009718-2: CAP, CERM, 0.047 uF, 16 V, +/- 10%, X5R, 0201; Manufacturer: MuRata; TaMin_C: -55°C; Polarized: N; SizeAreaWB_mm2: 2.08; Value1: Unknown; U/M: EA; TaMax_C: 85°C; SizeZ_mm: 0.33; SizeX_mm: 0.6; SizeY_mm: 0.3; Cap_Case: 0201; Value2: 16V; SizeArea_mm2: 0.18; Cap_F: 47nF; AEC Category: Q200
C74 C79 C83 C102 C103 = CMP-0009657-3: CAP, CERM, 2.2 uF, 6.3 V, +/- 20%, X5R, 0201; Manufacturer: Samsung Electro-Mechanics; AEC Category: Q200; Cap_Case: 0201; Cap_F: 2.2µF; Polarized: N; SizeArea_mm2: 0.18; SizeAreaWB_mm2: 2.08; SizeX_mm: 0.6; SizeY_mm: 0.3; SizeZ_mm: 0.26; TaMax_C: 85°C; TaMin_C: -55°C; U/M: EA; Value1: Unknown; Value2: 6.3V
C89 C90 = CMP-0081763-1: CAP, CERM, 1 µF, 6.3 V,+/- 10%, X6S, 0402; Manufacturer: TDK; TaMin_C: -55°C; Polarized: N; SizeAreaWB_mm2: 3; U/M: EA; Value: 1uF; TaMax_C: 105°C; SizeZ_mm: 0.6; SizeX_mm: 1; SizeY_mm: 0.5; Cap_Case: 0402; Value2: 6.3V; CompType: Capacitor; AEC Category: Q200
C91 C92 = CMP-0086440-1: as C130 on sheet PROC091G_AOP_IO
TP11 = CMP-0003825-1: 1mm Test Point, SMT; Manufacturer: Any
U2 = CMP-0860942-2: as U2 on sheet PROC091G_AOP_IO

## Sheet PROC091G_PMIC.SchDoc: PMIC
size 431 x 279 mm; Date: Not shown in title block; ApprovedBy: Not shown in title block; CheckedBy: Not shown in title block; Author: Not shown in title block; CompanyName: Not shown in title block; DrawnBy: Antony/Bala; Engineer: Not shown in title block; Organization: Not shown in title block; Address1: Not shown in title block; Address2: Not shown in title block; Address3: Not shown in title block; Address4: Not shown in title block; DocumentNumber: 5; Revision: Use project parameter SCH_Rev; SheetNumber: 5; SheetTotal: 12; PageSetup: Record=PageOptions¦CenterHorizontal=True¦CenterVertical=True¦PrintScale=1.00¦XCorrection=1.00¦YCorrection=1.00¦PrintKind=0¦BorderSize=5000000¦LeftOffset=0¦BottomOffset=0¦Orientation=2¦PaperLength=1000¦PaperWidth=1000¦Scale=100¦PaperSource=15¦PrintQuality=600¦MediaType=1¦DitherType=10¦PaperKind=Letter¦PrintScaleMode=1
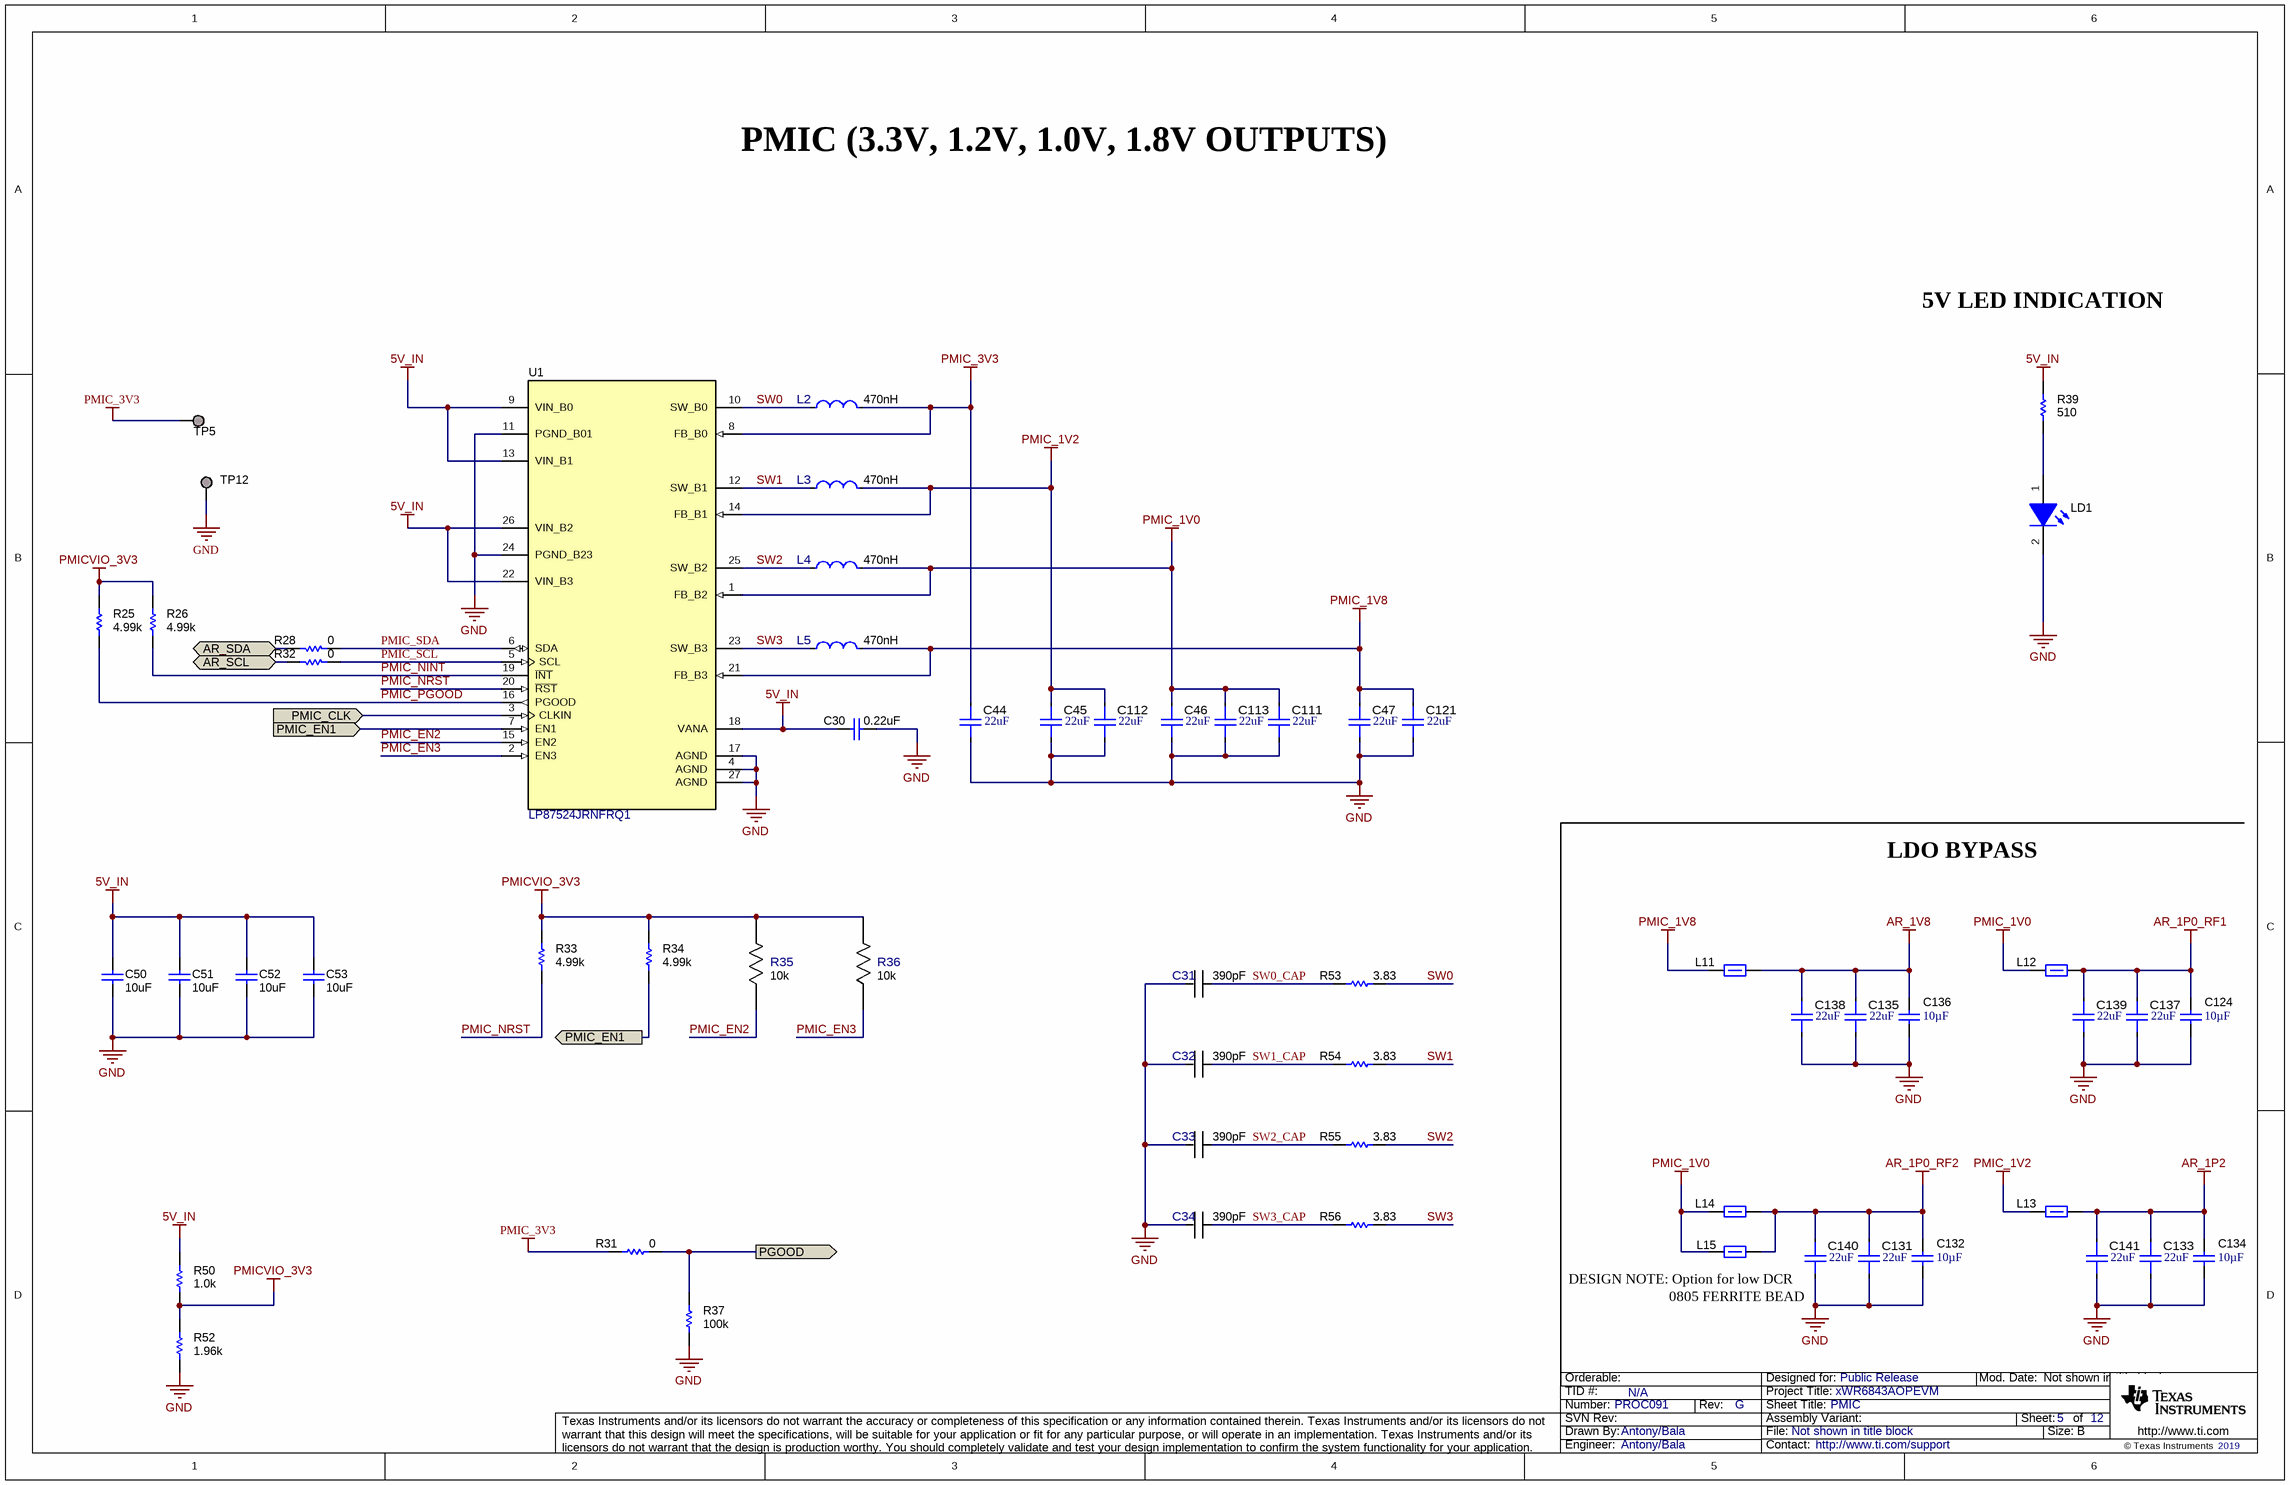
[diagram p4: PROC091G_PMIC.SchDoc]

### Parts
C30  value 0.22uF  [0201_033L]  (hidden comment: LMK063BJ224MP-F)
C31  Cap_F: 390pF  [FP-TMK063CG391JT-F_0201 (0603 Metric)-IPC_C]  (hidden comment: TMK063CG391JT-F)
C32  Cap_F: 390pF  [FP-TMK063CG391JT-F_0201 (0603 Metric)-IPC_C]  (hidden comment: TMK063CG391JT-F)
C33  Cap_F: 390pF  [FP-TMK063CG391JT-F_0201 (0603 Metric)-IPC_C]  (hidden comment: TMK063CG391JT-F)
C34  Cap_F: 390pF  [FP-TMK063CG391JT-F_0201 (0603 Metric)-IPC_C]  (hidden comment: TMK063CG391JT-F)
C44  ValueDisplayed: 22uF  [FP-CGA4J1X7T0J226M125AC_0805-MFG]  (hidden comment: CGA4J1X7T0J226M125AC)
C45  ValueDisplayed: 22uF  [FP-CGA4J1X7T0J226M125AC_0805-MFG]  (hidden comment: CGA4J1X7T0J226M125AC)
C46  ValueDisplayed: 22uF  [FP-CGA4J1X7T0J226M125AC_0805-MFG]  (hidden comment: CGA4J1X7T0J226M125AC)
C47  ValueDisplayed: 22uF  [FP-CGA4J1X7T0J226M125AC_0805-MFG]  (hidden comment: CGA4J1X7T0J226M125AC)
C50  value 10uF  [0402_070]  (hidden comment: CL05A106MP5NUNC)
C51  value 10uF  [0402_070]  (hidden comment: CL05A106MP5NUNC)
C52  value 10uF  [0402_070]  (hidden comment: CL05A106MP5NUNC)
C53  value 10uF  [0402_070]  (hidden comment: CL05A106MP5NUNC)
C111  ValueDisplayed: 22uF  [FP-CGA4J1X7T0J226M125AC_0805-MFG]  (hidden comment: CGA4J1X7T0J226M125AC)
C112  ValueDisplayed: 22uF  [FP-CGA4J1X7T0J226M125AC_0805-MFG]  (hidden comment: CGA4J1X7T0J226M125AC)
C113  ValueDisplayed: 22uF  [FP-CGA4J1X7T0J226M125AC_0805-MFG]  (hidden comment: CGA4J1X7T0J226M125AC)
C121  ValueDisplayed: 22uF  [FP-CGA4J1X7T0J226M125AC_0805-MFG]  (hidden comment: CGA4J1X7T0J226M125AC)
C124  Cap_F: 10µF  [0805_HV]  (hidden comment: GCM21BR71A106KE22L)
C131  ValueDisplayed: 22uF  [FP-CGA4J1X7T0J226M125AC_0805-MFG]  (hidden comment: CGA4J1X7T0J226M125AC)
C132  Cap_F: 10µF  [0805_HV]  (hidden comment: GCM21BR71A106KE22L)
C133  ValueDisplayed: 22uF  [FP-CGA4J1X7T0J226M125AC_0805-MFG]  (hidden comment: CGA4J1X7T0J226M125AC)
C134  Cap_F: 10µF  [0805_HV]  (hidden comment: GCM21BR71A106KE22L)
C135  ValueDisplayed: 22uF  [FP-CGA4J1X7T0J226M125AC_0805-MFG]  (hidden comment: CGA4J1X7T0J226M125AC)
C136  Cap_F: 10µF  [0805_HV]  (hidden comment: GCM21BR71A106KE22L)
C137  ValueDisplayed: 22uF  [FP-CGA4J1X7T0J226M125AC_0805-MFG]  (hidden comment: CGA4J1X7T0J226M125AC)
C138  ValueDisplayed: 22uF  [FP-CGA4J1X7T0J226M125AC_0805-MFG]  (hidden comment: CGA4J1X7T0J226M125AC)
C139  ValueDisplayed: 22uF  [FP-CGA4J1X7T0J226M125AC_0805-MFG]  (hidden comment: CGA4J1X7T0J226M125AC)
C140  ValueDisplayed: 22uF  [FP-CGA4J1X7T0J226M125AC_0805-MFG]  (hidden comment: CGA4J1X7T0J226M125AC)
C141  ValueDisplayed: 22uF  [FP-CGA4J1X7T0J226M125AC_0805-MFG]  (hidden comment: CGA4J1X7T0J226M125AC)
L2  Ind_H: 470nH  [FP-MCKK2012TR47M_0805 (2012 Metric)-IPC_C]  (hidden comment: MCKK2012TR47M)
L3  Ind_H: 470nH  [FP-MCKK2012TR47M_0805 (2012 Metric)-IPC_C]  (hidden comment: MCKK2012TR47M)
L4  Ind_H: 470nH  [FP-MCKK2012TR47M_0805 (2012 Metric)-IPC_C]  (hidden comment: MCKK2012TR47M)
L5  Ind_H: 470nH  [FP-MCKK2012TR47M_0805 (2012 Metric)-IPC_C]  (hidden comment: MCKK2012TR47M)
L11  BLM18KG121TH1D  [0603]  (value not drawn)
L12  BLM18KG121TH1D  [0603]  (value not drawn)
L13  BLM18KG121TH1D  [0603]  (value not drawn)
L14  BLM18KG121TH1D  [0603]  (value not drawn)
L15  BLM21PG221SN1D  [0805L]  (value not drawn)
LD1  APHHS1005CGCK  [APHHS1005_Green]  (value not drawn)
R25  value 4.99k  [0201L]  (hidden comment: RC0201FR-074K99L)
R26  value 4.99k  [0201L]  (hidden comment: RC0201FR-074K99L)
R28  Res_ohm: 0  [FP-RC0201JR-070RL_0201 (0603 Metric)-MFG]  (hidden comment: RC0201JR-070RL)
R31  Res_ohm: 0  [FP-RC0201JR-070RL_0201 (0603 Metric)-MFG]  (hidden comment: RC0201JR-070RL)
R32  Res_ohm: 0  [FP-RC0201JR-070RL_0201 (0603 Metric)-MFG]  (hidden comment: RC0201JR-070RL)
R33  value 4.99k  [0201L]  (hidden comment: RC0201FR-074K99L)
R34  value 4.99k  [0201L]  (hidden comment: RC0201FR-074K99L)
R35  Res_ohm: 10k  [FP-RR0306P-103-D_0201-IPC_C]  (hidden comment: RR0306P-103-D)
R36  Res_ohm: 10k  [FP-RR0306P-103-D_0201-IPC_C]  (hidden comment: RR0306P-103-D)
R37  value 100k  [0201L]  (hidden comment: CRCW0201100KFKED)
R39  value 510  [0201L]  (hidden comment: RC0201JR-07510RL)
R50  value 1.0k  [0201L]  (hidden comment: RC0201JR-071KL)
R52  value 1.96k  [0201L]  (hidden comment: RC0201FR-071K96L)
R53  Res_ohm: 3.83  [FP-RC0402FR-073R83L_0402 (1005 Metric)-IPC_C]  (hidden comment: RC0402FR-073R83L)
R54  Res_ohm: 3.83  [FP-RC0402FR-073R83L_0402 (1005 Metric)-IPC_C]  (hidden comment: RC0402FR-073R83L)
R55  Res_ohm: 3.83  [FP-RC0402FR-073R83L_0402 (1005 Metric)-IPC_C]  (hidden comment: RC0402FR-073R83L)
R56  Res_ohm: 3.83  [FP-RC0402FR-073R83L_0402 (1005 Metric)-IPC_C]  (hidden comment: RC0402FR-073R83L)
TP5  TESTPOINT  [TP_25MIL-SMT]  (value not drawn)  (no BOM)
TP12  TESTPOINT  [TP_VIA_060RND040]  (value not drawn)  (no BOM)
U1  LP87524JRNFRQ1  [RNF0026C]

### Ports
AR_SCL (bidir), AR_SDA (bidir), PGOOD (out), PMIC_CLK (in), PMIC_EN1 (in), PMIC_EN1 (out)

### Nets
5V_IN: C30.1 C50.1 C51.1 C52.1 C53.1 R39.1 R50.2 U1.9(VIN_B0) U1.13(VIN_B1) U1.18(VANA) U1.22(VIN_B3) U1.26(VIN_B2)
AR_1P0_RF1: C124.1 C137.1 C139.1 L12.2
AR_1P0_RF2: C131.1 C132.1 C140.1 L14.2 L15.2
AR_1P2: C133.1 C134.1 C141.1 L13.2
AR_1V8: C135.1 C136.1 C138.1 L11.2
GND: C30.2 C31.2 C32.2 C33.2 C34.2 C44.2 C45.2 C46.2 C47.2 C50.2 C51.2 C52.2 C53.2 C111.2 C112.2 C113.2 C121.2 C124.2 C131.2 C132.2 C133.2 C134.2 C135.2 C136.2 C137.2 C138.2 C139.2 C140.2 C141.2 LD1.2(K) R37.1 R52.1 TP12.1 U1.4(AGND) U1.11(PGND_B01) U1.17(AGND) U1.24(PGND_B23) U1.27(AGND)
PMIC_1V0: C46.1 C111.1 C113.1 L4.1 L12.1 L14.1 L15.1 U1.1(FB_B2)
PMIC_1V2: C45.1 C112.1 L3.1 L13.1 U1.14(FB_B1)
PMIC_1V8: C47.1 C121.1 L5.1 L11.1 U1.21(FB_B3)
PMIC_3V3: C44.1 L2.1 R31.2 TP5.1 U1.8(FB_B0)
PMICVIO_3V3: R25.2 R26.2 R33.2 R34.2 R35.2 R36.2 R50.1 R52.2
AR_SCL: R32.1 ; port AR_SCL
AR_SDA: R28.1 ; port AR_SDA
PGOOD: R31.1 R37.2 ; port PGOOD
PMIC_CLK: U1.3(CLKIN) ; port PMIC_CLK
PMIC_EN1: R34.1 U1.7(EN1) ; port PMIC_EN1
PMIC_EN2: R35.1 U1.15(EN2)
PMIC_EN3: R36.1 U1.2(EN3)
PMIC_NINT: R26.1 U1.19(~{INT})
PMIC_NRST: R33.1 U1.20(~{RST})
PMIC_PGOOD: R25.1 U1.16(PGOOD)
PMIC_SCL: R32.2 U1.5(SCL)
PMIC_SDA: R28.2 U1.6(SDA)
SW0: L2.2 R53.2 U1.10(SW_B0)
SW0_CAP: C31.1 R53.1
SW1: L3.2 R54.2 U1.12(SW_B1)
SW1_CAP: C32.1 R54.1
SW2: L4.2 R55.2 U1.25(SW_B2)
SW2_CAP: C33.1 R55.1
SW3: L5.2 R56.2 U1.23(SW_B3)
SW3_CAP: C34.1 R56.1
NetLD1_1: LD1.1(A) R39.2

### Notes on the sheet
- PMIC (3.3V, 1.2V, 1.0V, 1.8V OUTPUTS)
- 5V LED INDICATION
- LDO BYPASS
- DESIGN NOTE: Option for low DCR
- 0805 FERRITE BEAD

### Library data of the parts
C30 = CMP-0009781-1: as C56 on sheet PROC091G_AOP_PWR
C31-C34 = CMP-0086438-1: CAP CER 390PF 25V C0G/NP0 0201; Manufacturer: Taiyo Yuden; AEC Qualified: No; SizeZ_mm: 0.33mm; Symbol Name: SYM-TMK063CG391JT-F; TempCo: 30ppm/°C; Tolerance_%: 5%
C44-C47 C111-C113 C121 C131 C133 C135 C137-C141 = CMP-0091983-1: 22µF ±20% 6.3V Ceramic Capacitor X7T 0805 (2012 Metric); Manufacturer: TDK; AEC Qualified: Yes; AEC Grade: Grade 1; TempCo: +22/-33%; SizeZ_mm: 1.55mm
C50-C53 = CMP-0006339-4: as C55 on sheet PROC091G_AOP_PWR
C124 C132 C134 C136 = CMP-0008017-1: CAP, CERM, 10 uF, 10 V, +/- 10%, X7R, 0805; Manufacturer: MuRata; TaMin_C: -55°C; Polarized: N; SizeAreaWB_mm2: 6.75; Value1: Unknown; U/M: EA; Value: 10uF; TaMax_C: 125°C; SizeZ_mm: 1.45; SizeX_mm: 2; SizeY_mm: 1.25; Cap_Case: 0805; Value2: 10V; SizeArea_mm2: 2.5; AEC Category: Q200
L2-L5 = CMP-0087178-1: FIXED IND 470NH 4.5A 39 MOHM SMD; Manufacturer: Taiyo Yuden; AEC Qualified: No; DCR_ohm: 0.032; Irms: 3.1A; Material: Metal; SizeZ_mm: 1mm; Symbol Name: SYM-MCKK2012TR47M
L11-L14 = CMP-0077879-1: Ferrite Bead, 120 ohm @ 100 MHz, 1.9 A, 0603; Manufacturer: MuRata; ZTyp@100MHz_Ohm: 120; SizeAreaWB_mm2: 4.68; DCR_ohm: 0.04; Value1: 0.04 ohm; Value: 120 ohm; Imax_A: 1.9A; SizeZ_mm: 1.0; SizeX_mm: 1.6; SizeY_mm: 0.8; SizeArea_mm2: 1.28
L15 = CMP-0003363-1: Ferrite Bead, 220 ohm @ 100 MHz, 2 A, 0805; Manufacturer: MuRata; ZTyp@100MHz_Ohm: 220; SizeAreaWB_mm2: 6.75; DCR_ohm: 0.045; Value1: 0.045 ohm; Value: 220 ohm; Imax_A: 2A; SizeZ_mm: 1.45; SizeX_mm: 2; SizeY_mm: 1.25; SizeArea_mm2: 2.5
LD1 = CMP-0067682-2: LED, Green, SMD; Manufacturer: Kingbright; Angle: 120.0; Power_TotalModule: 75mW; SizeZ_mm: 0.6; Vf_V: 2.1V; Vr_V: 5V; Io_A: 20mA; Ir_A: 10µA; SizeArea_mm2: 0.5; SizeAreaWB_mm2: 3.0; SizeX_mm: 1.0; Tjmax_C: 85°C; Value1: 0.075W
R25 R26 R33 R34 = CMP-0027745-1: RES, 4.99 k, 1%, 0.05 W, 0201; Manufacturer: Yageo America; AEC Category: Q200; AEC Qualified: N; EIA_Code: E96; Power_W: 50mW; SizeArea_mm2: 0.18; SizeX_mm: 0.6; SizeY_mm: 0.3; SizeZ_mm: 0.26; TempCo: 200 ppm/C; U/M: EA; Value2: 0.05W; Value_Code: 4k99; VDC_V: 25V
R28 R31 R32 = CMP-0086442-2: as R2 on sheet PROC091G_AOP_IO
R35 R36 = CMP-0088002-1: as R3 on sheet PROC091G_AOP_IO
R37 = CMP-0027261-3: as R4 on sheet PROC091G_AOP_IO
R39 = CMP-0027137-1: RES, 510, 5%, 0.05 W, 0201; Manufacturer: Yageo America; AEC Category: Q200; AEC Qualified: N; EIA_Code: E24; Power_W: 50mW; SizeArea_mm2: 0.18; SizeX_mm: 0.6; SizeY_mm: 0.3; SizeZ_mm: 0.26; TempCo: 200 ppm/C; U/M: EA; Value2: 0.05W; Value_Code: 510R; VDC_V: 25V
R50 = CMP-0027052-1: as R75 on sheet PROC091G_AOP_IO
R52 = CMP-0027452-1: RES, 1.96 k, 1%, 0.05 W, 0201; Manufacturer: Yageo America; AEC Category: Q200; AEC Qualified: N; EIA_Code: E96; Power_W: 50mW; SizeArea_mm2: 0.18; SizeX_mm: 0.6; SizeY_mm: 0.3; SizeZ_mm: 0.26; TempCo: 200 ppm/C; U/M: EA; Value2: 0.05W; Value_Code: 1k96; VDC_V: 25V
R53-R56 = CMP-0086444-2: RES Thick Film SMD 3.83Ω 1% 1/16W 0402 200ppm/°C; Manufacturer: Yageo; AEC Qualified: No; Power_W: 63mW; VDC_V: 50V; SizeZ_mm: 0.4mm
TP5 TP12 = CMP-0078143-3: TEST POINT.  No entry in BOM.
U1 = CMP-0079120-2: 4-A + 2.5-A + Two 1.5-A Buck Converters With Integrated Switches, RNF0026C (VQFN-HR-26); Alternate PartNumber: LP87524JRNFTQ1; Alternate Manufacturer: Texas Instruments; SizeAreaWB_mm2: 27.5; SizeZ_mm: 0.9; SizeX_mm: 4; SizeY_mm: 4.5; SizeArea_mm2: 18; CompType: IC; AEC Qualified: Y; AEC Category: Q200

## Sheet PROC091G_FLASH_USB_TO_UART.SchDoc: FLASH&USB_TO_UART
size 431 x 279 mm; Date: Not shown in title block; ApprovedBy: Not shown in title block; CheckedBy: Not shown in title block; Author: Not shown in title block; CompanyName: Not shown in title block; DrawnBy: Antony/Bala; Engineer: Not shown in title block; Organization: Not shown in title block; Address1: Not shown in title block; Address2: Not shown in title block; Address3: Not shown in title block; Address4: Not shown in title block; DocumentNumber: 6; Revision: Use project parameter SCH_Rev; SheetNumber: 6; SheetTotal: 12; PageSetup: Record=PageOptions¦CenterHorizontal=True¦CenterVertical=True¦PrintScale=1.00¦XCorrection=1.00¦YCorrection=1.00¦PrintKind=0¦BorderSize=5000000¦LeftOffset=0¦BottomOffset=0¦Orientation=2¦PaperLength=1000¦PaperWidth=1000¦Scale=100¦PaperSource=15¦PrintQuality=600¦MediaType=1¦DitherType=10¦PaperKind=Letter¦PrintScaleMode=1
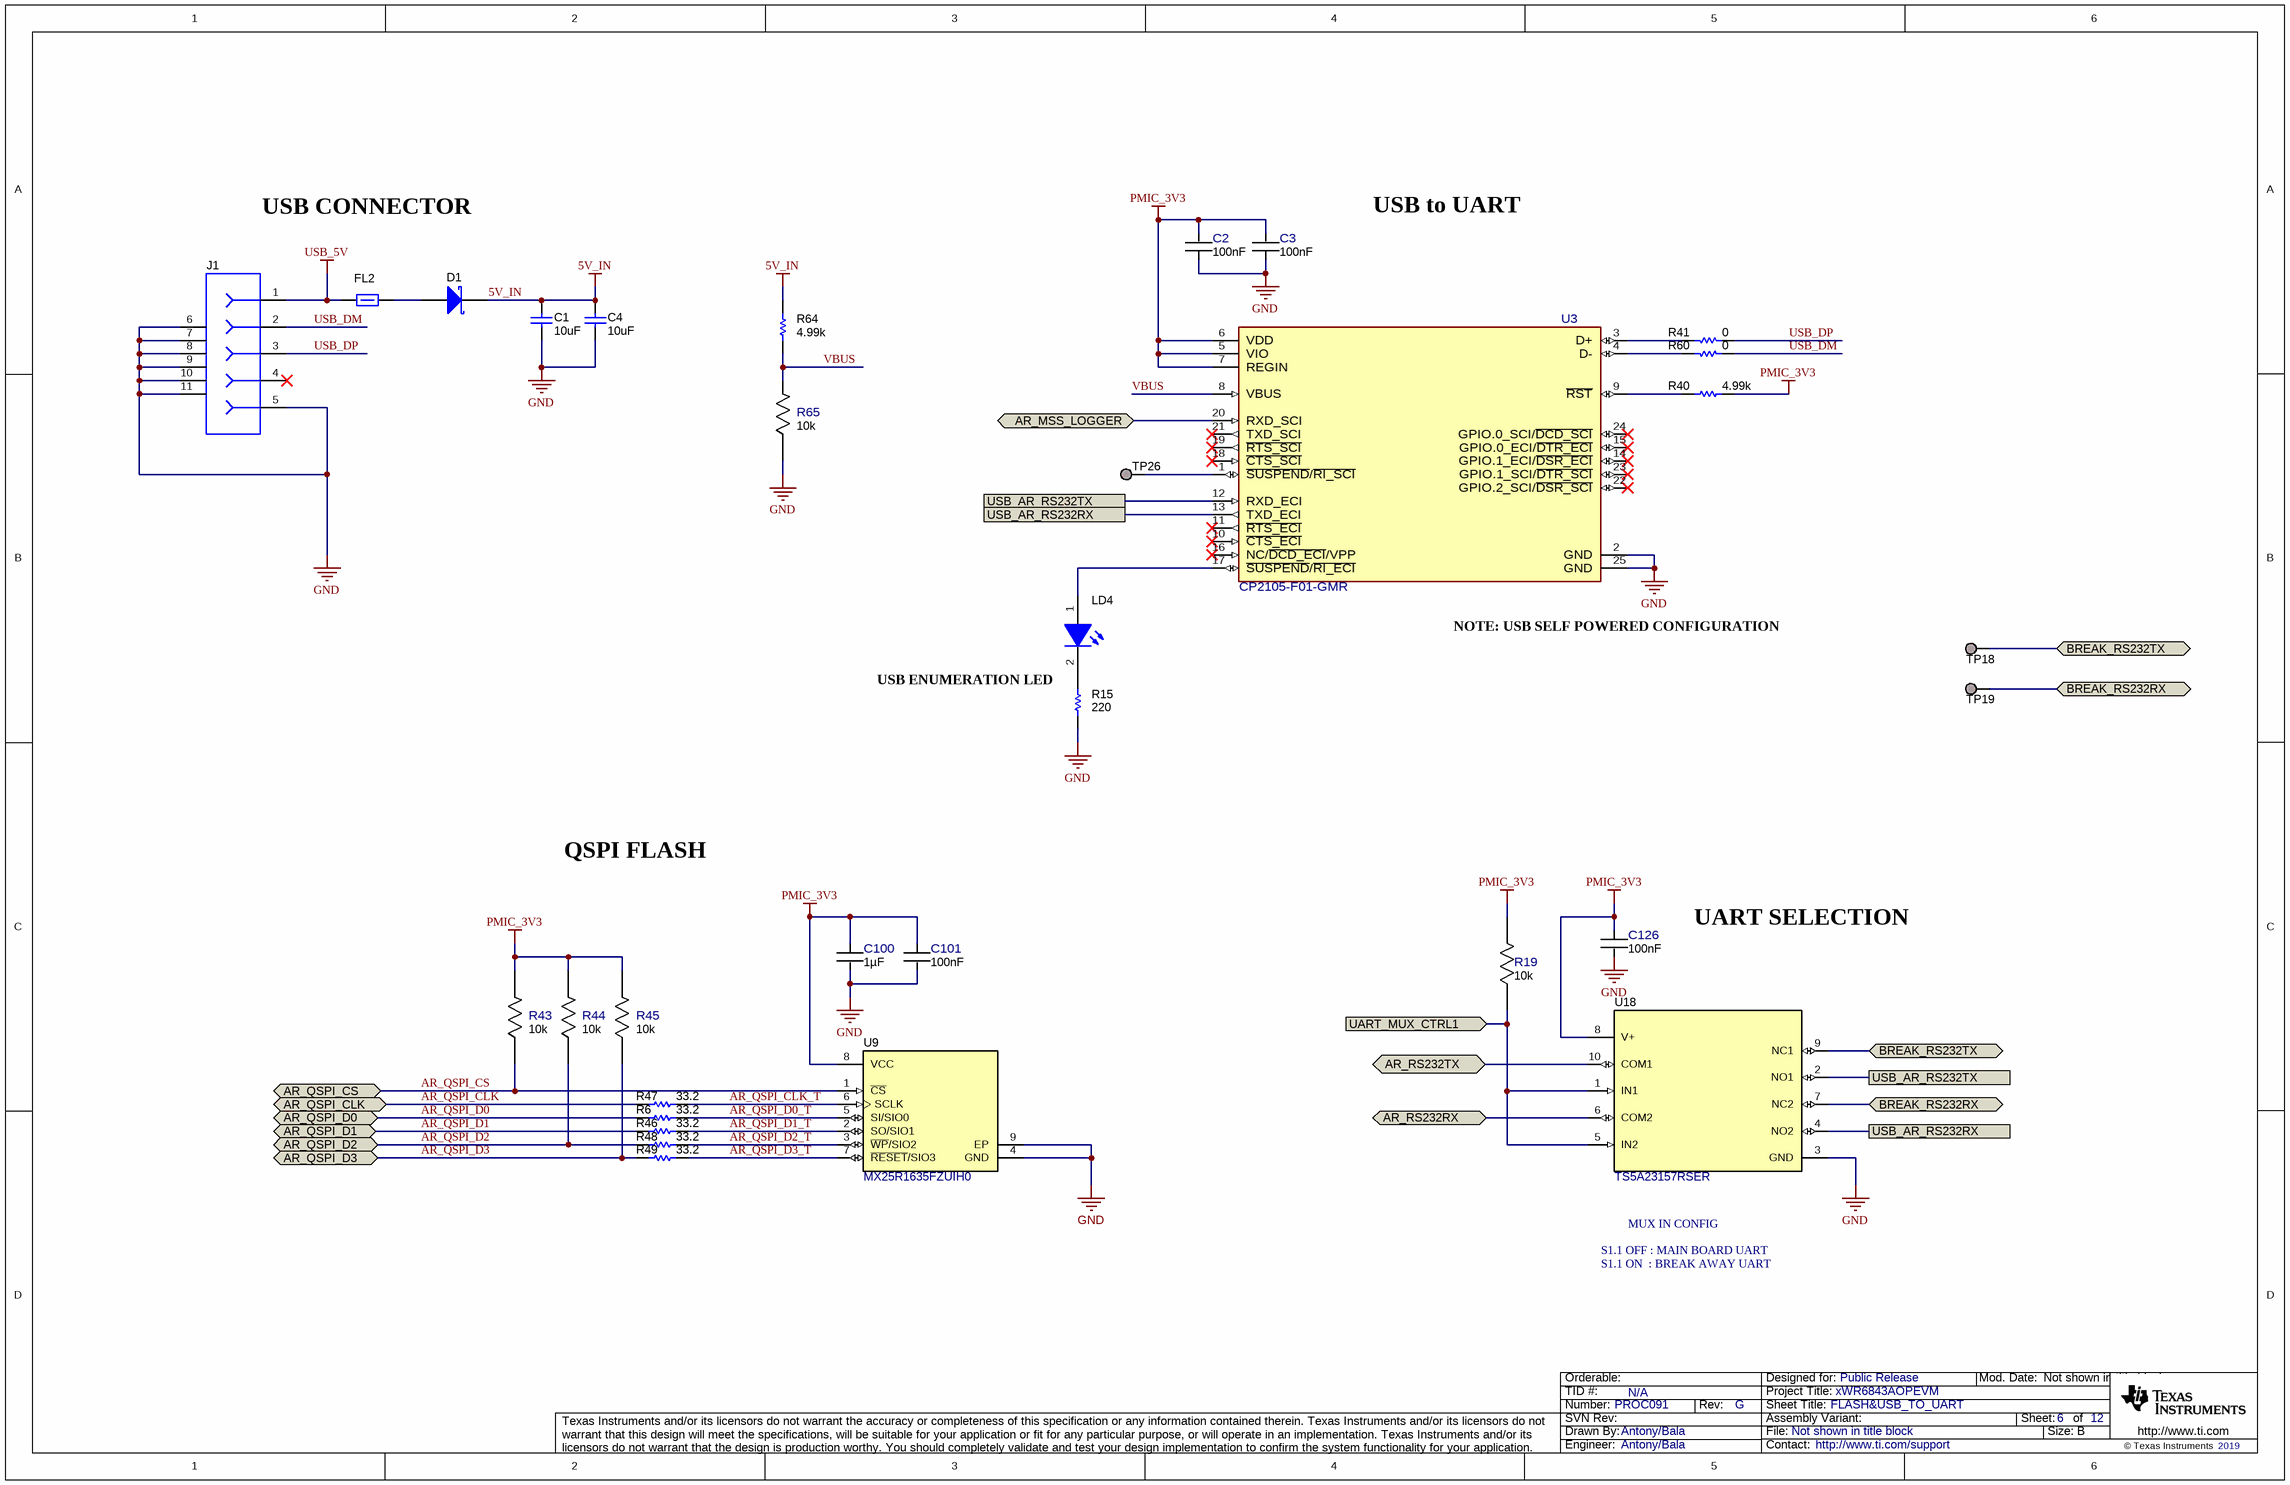
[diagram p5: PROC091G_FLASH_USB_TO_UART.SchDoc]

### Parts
C1  value 10uF  [0402_070]  (hidden comment: CL05A106MP5NUNC)
C2  Cap_F: 100nF  [FP-GRM033R6YA104KE14D_0201 (0603 Metric)-IPC_C]  (hidden comment: GRM033R6YA104KE14D)
C3  Cap_F: 100nF  [FP-GRM033R6YA104KE14D_0201 (0603 Metric)-IPC_C]  (hidden comment: GRM033R6YA104KE14D)
C4  value 10uF  [0402_070]  (hidden comment: CL05A106MP5NUNC)
C100  Cap_F: 1µF  [FP-CL03A105MO3NRNH_0201-IPC_C]  (hidden comment: CL03A105MO3NRNH)
C101  Cap_F: 100nF  [FP-GRM033R6YA104KE14D_0201 (0603 Metric)-IPC_C]  (hidden comment: GRM033R6YA104KE14D)
C126  Cap_F: 100nF  [FP-GRM033R6YA104KE14D_0201 (0603 Metric)-IPC_C]  (hidden comment: GRM033R6YA104KE14D)
D1  NSR20F30NXT5G  [DSN2_0603]  (value not drawn)
FL2  BLM15PD300SZ1D  [0402L]  (value not drawn)
J1  105017-0001  [CONN_105017-0001]  (value not drawn)
LD4  APHHS1005CGCK  [APHHS1005_Green]  (value not drawn)
R6  value 33.2  [0201L]  (hidden comment: CRCW020133R2FNED)
R15  value 220  [0201L]  (hidden comment: RC0201JR-07220RL)
R19  Res_ohm: 10k  [FP-RR0306P-103-D_0201-IPC_C]  (hidden comment: RR0306P-103-D)
R40  value 4.99k  [0201L]  (hidden comment: RC0201FR-074K99L)
R41  Res_ohm: 0  [FP-RC0201JR-070RL_0201 (0603 Metric)-MFG]  (hidden comment: RC0201JR-070RL)
R43  Res_ohm: 10k  [FP-RR0306P-103-D_0201-IPC_C]  (hidden comment: RR0306P-103-D)
R44  Res_ohm: 10k  [FP-RR0306P-103-D_0201-IPC_C]  (hidden comment: RR0306P-103-D)
R45  Res_ohm: 10k  [FP-RR0306P-103-D_0201-IPC_C]  (hidden comment: RR0306P-103-D)
R46  value 33.2  [0201L]  (hidden comment: CRCW020133R2FNED)
R47  value 33.2  [0201L]  (hidden comment: CRCW020133R2FNED)
R48  value 33.2  [0201L]  (hidden comment: CRCW020133R2FNED)
R49  value 33.2  [0201L]  (hidden comment: CRCW020133R2FNED)
R60  Res_ohm: 0  [FP-RC0201JR-070RL_0201 (0603 Metric)-MFG]  (hidden comment: RC0201JR-070RL)
R64  value 4.99k  [0201L]  (hidden comment: RC0201FR-074K99L)
R65  Res_ohm: 10k  [FP-RR0306P-103-D_0201-IPC_C]  (hidden comment: RR0306P-103-D)
TP18  TESTPOINT  [TP_25MIL-SMT]  (value not drawn)  (no BOM)
TP19  TESTPOINT  [TP_25MIL-SMT]  (value not drawn)  (no BOM)
TP26  TESTPOINT  [TP_25MIL-SMT]  (value not drawn)  (no BOM)
U3  CP2105-F01-GMR  [FP-CP2105-F01-GMR_QFN24-EP-IPC_A]
U9  MX25R1635FZUIH0  [USON-8L]
U18  TS5A23157RSER  [RSE0010A]

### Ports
AR_MSS_LOGGER (bidir), AR_QSPI_CLK (bidir), AR_QSPI_CS (bidir), AR_QSPI_D0 (bidir), AR_QSPI_D1 (bidir), AR_QSPI_D2 (bidir), AR_QSPI_D3 (bidir), AR_RS232RX (bidir), AR_RS232TX (bidir), BREAK_RS232RX (bidir), BREAK_RS232TX (bidir), UART_MUX_CTRL1 (in), USB_AR_RS232RX, USB_AR_RS232TX

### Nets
5V_IN: C1.2 C4.1 D1.1(K) R64.1
GND: C1.1 C2.1 C3.1 C4.2 C100.2 C101.2 C126.2 J1.5 J1.6 J1.7 J1.8 J1.9 J1.10 J1.11 R15.1 R65.1 U3.2(GND) U3.25(GND) U9.4(GND) U9.9(EP) U18.3(GND)
PMIC_3V3: C2.2 C3.2 C100.1 C101.1 C126.1 R19.2 R40.1 R43.2 R44.2 R45.2 U3.5(VIO) U3.6(VDD) U3.7(REGIN) U9.8(VCC) U18.8(V+)
USB_5V: FL2.1 J1.1
AR_MSS_LOGGER: U3.20(RXD_SCI) ; port AR_MSS_LOGGER
AR_QSPI_CLK: R47.1 ; port AR_QSPI_CLK
AR_QSPI_CLK_T: R47.2 U9.6(SCLK)
AR_QSPI_CS: R43.1 U9.1(~{CS}) ; port AR_QSPI_CS
AR_QSPI_D0: R6.1 ; port AR_QSPI_D0
AR_QSPI_D0_T: R6.2 U9.5(SI/SIO0)
AR_QSPI_D1: R46.1 ; port AR_QSPI_D1
AR_QSPI_D1_T: R46.2 U9.2(SO/SIO1)
AR_QSPI_D2: R44.1 R48.1 ; port AR_QSPI_D2
AR_QSPI_D2_T: R48.2 U9.3(~{WP}/SIO2)
AR_QSPI_D3: R45.1 R49.1 ; port AR_QSPI_D3
AR_QSPI_D3_T: R49.2 U9.7(~{RESET}/SIO3)
AR_RS232RX: U18.6(COM2) ; port AR_RS232RX
AR_RS232TX: U18.10(COM1) ; port AR_RS232TX
BREAK_RS232RX: TP19.1 U18.7(NC2) ; port BREAK_RS232RX
BREAK_RS232TX: TP18.1 U18.9(NC1) ; port BREAK_RS232TX
UART_MUX_CTRL1: R19.1 U18.1(IN1) U18.5(IN2) ; port UART_MUX_CTRL1
USB_AR_RS232RX: U3.13(TXD_ECI) U18.4(NO2) ; port USB_AR_RS232RX
USB_AR_RS232TX: U3.12(RXD_ECI) U18.2(NO1) ; port USB_AR_RS232TX
USB_DM: J1.2 R60.2
USB_DP: J1.3 R41.2
VBUS: R64.2 R65.2 U3.8(VBUS)
NetD1_2: D1.2(A) FL2.2
NetLD4_1: LD4.1(A) U3.17(~{SUSPEND}/~{RI_ECI})
NetLD4_2: LD4.2(K) R15.2
NetR40_2: R40.2 U3.9(~{RST})
NetR41_1: R41.1 U3.3(D+)
NetR60_1: R60.1 U3.4(D-)
NetTP26_1: TP26.1 U3.1(~{SUSPEND}/~{RI_SCI})

Not connected (* = marked no-connect by the designer): J1 4*; U3 10(~{CTS_ECI})* 11(~{RTS_ECI})* 14(GPIO.1_ECI/~{DSR_ECI})* 15(GPIO.0_ECI/~{DTR_ECI})* 16(NC/~{DCD_ECI}/VPP)* 18(~{CTS_SCI})* 19(~{RTS_SCI})* 21(TXD_SCI)* 22(GPIO.2_SCI/~{DSR_SCI})* 23(GPIO.1_SCI/~{DTR_SCI})* 24(GPIO.0_SCI/~{DCD_SCI})*

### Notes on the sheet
- USB CONNECTOR
- USB to UART
- (near U3) NOTE: USB SELF POWERED CONFIGURATION
- USB ENUMERATION LED
- QSPI FLASH
- UART SELECTION
- MUX IN CONFIG
- S1.1 ON  : BREAK AWAY UART
- S1.1 OFF : MAIN BOARD UART

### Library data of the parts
C1 C4 = CMP-0006339-4: as C55 on sheet PROC091G_AOP_PWR
C2 C3 C101 C126 = CMP-0086440-1: as C130 on sheet PROC091G_AOP_IO
C100 = CMP-0086446-1: 1µF ±20% 16V Ceramic Capacitor X5R 0201; Manufacturer: Samsung Electro-Mechanics; AEC Qualified: No; SizeZ_mm: 0.39mm; Symbol Name: SYM-CL03A105MO3NRNH; TempCo: 15%
D1 = CMP-0028829-2: Diode, Schottky, 30 V, 2 A, 2-XFDFN; Manufacturer: ON Semiconductor; Value2: 0.48V; SizeY_mm: 0.8; Value: 30V; TJmax_C: 150°C; Green_Lifecycle: Not Set; SizeAreaWB_mm2: 4.68; Value1: 2A; SizeArea_mm2: 1.28; Green_REACh: Incomplete; AEC Category: Q101; SizeZ_mm: 0.31; Vf_V: 480mV; AEC Qualified: N; SizeX_mm: 1.6
FL2 = CMP-0078934-1: Inductor, Ferrite Bead, Ferrite, 2.2 A, 0.035 ohm, AEC-Q200 Grade 1, SMD; Manufacturer: MuRata; AEC Category: Q200; AEC Grade: 1; AEC Qualified: Y; DCR_ohm: 0.035; Imax_A: 2.2A; SizeArea_mm2: 0.5; SizeAreaWB_mm2: 3; SizeZ_mm: 0.6
J1 = CMP-0055293-1: Connector, Receptacle, Micro-USB Type B, R/A, Bottom Mount SMT; Manufacturer: Molex; CNHeader: FALSE; CompType: USB; CT: TRUE; Gender: Female; Green_Lifecycle: Active; Green_REACh: Passed
LD4 = CMP-0067682-2: as LD1 on sheet PROC091G_PMIC
R6 R46-R49 = CMP-0027275-3: RES, 33.2, 1%, 0.05 W, 0201; Manufacturer: Vishay-Dale; AEC Category: Q200; AEC Qualified: N; EIA_Code: E96; Power_W: 50mW; SizeArea_mm2: 0.18; SizeX_mm: 0.6; SizeY_mm: 0.3; SizeZ_mm: 0.26; TempCo: 200 ppm/C; Value2: 0.05W; Value_Code: 33R2
R15 = CMP-0027072-1: RES, 220, 5%, 0.05 W, 0201; Manufacturer: Yageo America; AEC Category: Q200; AEC Qualified: N; EIA_Code: E24; Power_W: 50mW; SizeArea_mm2: 0.18; SizeX_mm: 0.6; SizeY_mm: 0.3; SizeZ_mm: 0.26; TempCo: 200 ppm/C; U/M: EA; Value2: 0.05W; Value_Code: 220R; VDC_V: 25V
R19 R43-R45 R65 = CMP-0088002-1: as R3 on sheet PROC091G_AOP_IO
R40 R64 = CMP-0027745-1: as R25 on sheet PROC091G_PMIC
R41 R60 = CMP-0086442-2: as R2 on sheet PROC091G_AOP_IO
TP18 TP19 TP26 = CMP-0078143-3: TEST POINT.  No entry in BOM.
U3 = CMP-0087172-1: I/O Controller Interface IC USB to Dual UART bridge; Manufacturer: Silicon Labs; SizeZ_mm: 0.8mm
U9 = CMP-0078466-1: ULTRA LOW POWER, 16M-BIT [x 1/x 2/x 4] CMOS MXSMIO (SERIAL MULTI I/O) FLASH MEMORY, SON-8; Manufacturer: Macronix International Co., LTD; SizeArea_mm2: 6; SizeAreaWB_mm2: 12; SizeX_mm: 3; SizeY_mm: 2; SizeZ_mm: 0.6
U18 = CMP-0074545-1: Dual 10-ohm SPDT Analog Switch, RSE0010A (UQFN-10); Alternate Manufacturer: Texas Instruments; CompType: IC; SizeArea_mm2: 3.0; SizeAreaWB_mm2: 7.5; SizeX_mm: 1.5; SizeY_mm: 2.0; SizeZ_mm: 0.6; U/M: EA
